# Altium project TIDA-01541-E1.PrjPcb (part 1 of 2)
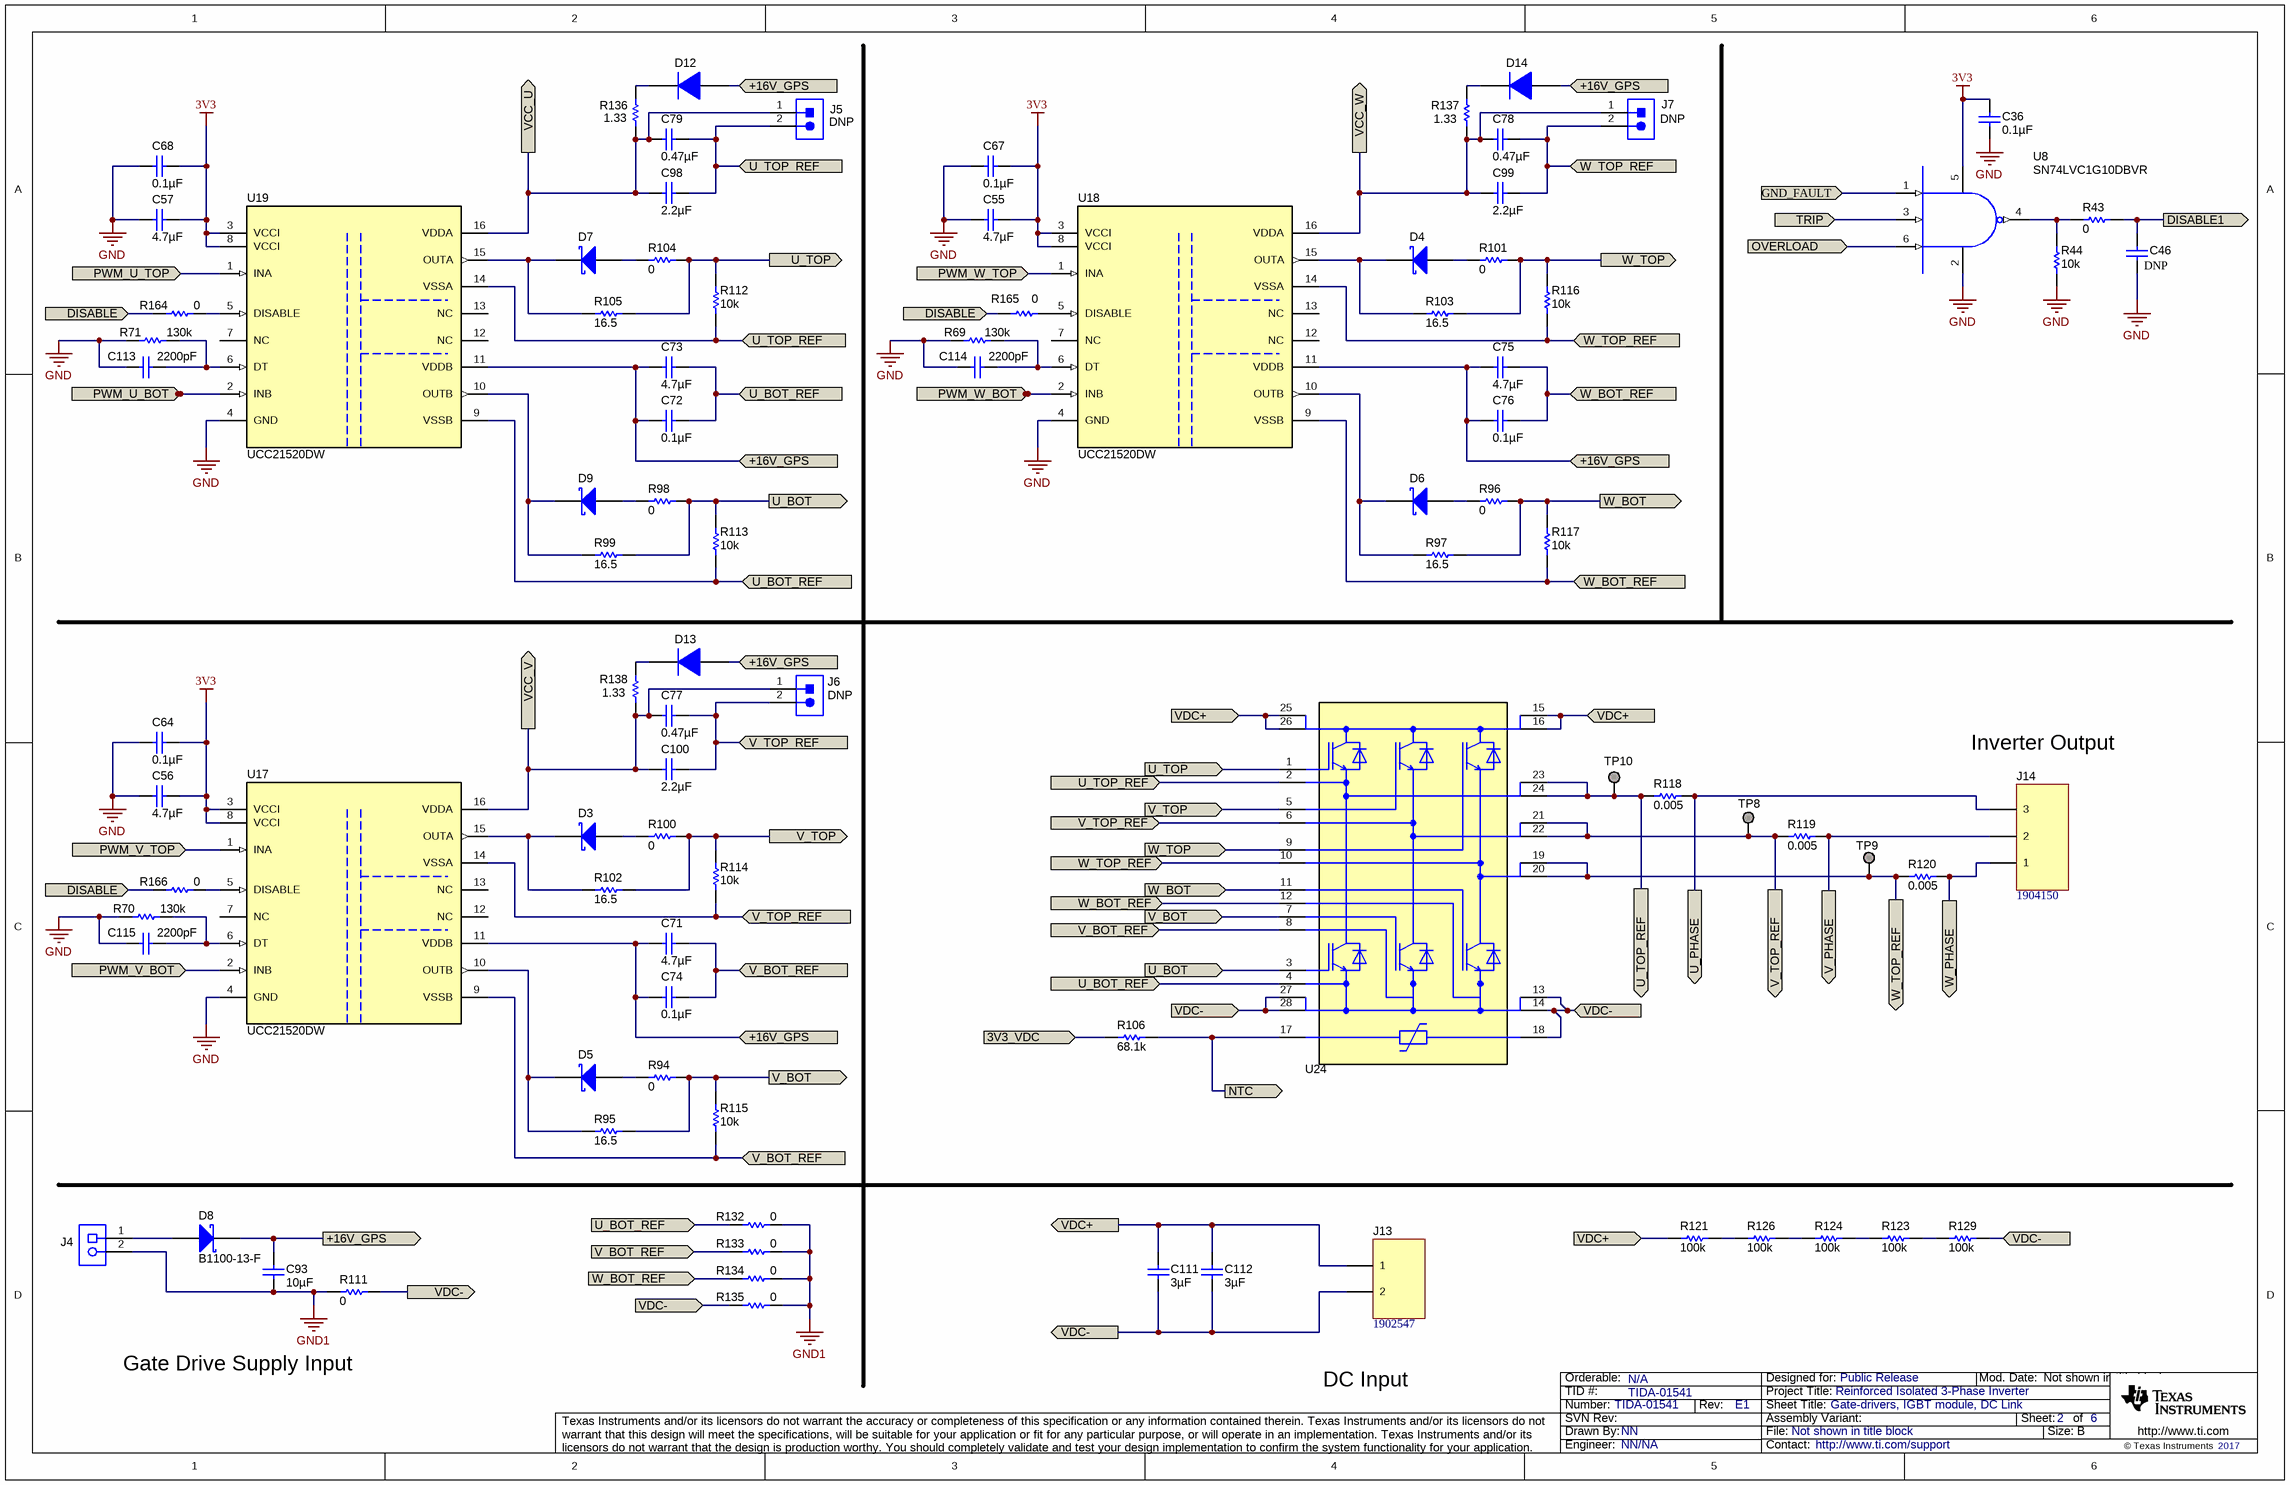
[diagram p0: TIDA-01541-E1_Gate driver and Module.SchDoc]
CopyrightYear: 2017; EVM_Orderable: N/A; PCB_Layout: Avinash N; PCB_Rev: E1; PRJ_Customer: Public Release; PRJ_Engineer: NN/NA; PRJ_Number: TIDA-01541; PRJ_Title: Reinforced Isolated 3-Phase Inverter; SCH_Rev: E1; TechSupport: http://www.ti.com/support; TID: TIDA-01541
5 sheets, 370 parts. Net scope: flat (ports and power ports of the same name join across sheets).
Board file: TIDA-01541-E1.PcbDoc
Sheets:
  TIDA-01541-E1_Gate driver and Module.SchDoc
  TIDA-01541-E1_Current sense.SchDoc
  TIDA-01541-E1_DC BUS and TEMP Sense.SchDoc
  TIDA-01541-E1_MCU Interface.SchDoc
  TIDA-01541-E1_EVM_Hardware.SchDoc

## Sheet TIDA-01541-E1_Gate driver and Module.SchDoc: Gate-drivers, IGBT module, DC Link
size 431 x 279 mm; Date: Not shown in title block; ApprovedBy: Not shown in title block; CheckedBy: Not shown in title block; Author: Not shown in title block; CompanyName: Not shown in title block; DrawnBy: NN; Engineer: Not shown in title block; Organization: Not shown in title block; Address1: Not shown in title block; Address2: Not shown in title block; Address3: Not shown in title block; Address4: Not shown in title block; DocumentNumber: 1; Revision: Use project parameter SCH_Rev; SheetNumber: 2; SheetTotal: 6

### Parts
C36  ValueDisplayed: 0.1µF  [0603]  (hidden comment: GRM188R71H104KA93D)
C46  885012206040  [0603]  (value not drawn)
C55  ValueDisplayed: 4.7µF  [0805_HV]  (hidden comment: C2012X5R1H475K125AB)
C56  ValueDisplayed: 4.7µF  [0805_HV]  (hidden comment: C2012X5R1H475K125AB)
C57  ValueDisplayed: 4.7µF  [0805_HV]  (hidden comment: C2012X5R1H475K125AB)
C64  ValueDisplayed: 0.1µF  [0603]  (hidden comment: GRM188R71H104KA93D)
C67  ValueDisplayed: 0.1µF  [0603]  (hidden comment: GRM188R71H104KA93D)
C68  ValueDisplayed: 0.1µF  [0603]  (hidden comment: GRM188R71H104KA93D)
C71  ValueDisplayed: 4.7µF  [0805_HV]  (hidden comment: C2012X5R1H475K125AB)
C72  ValueDisplayed: 0.1µF  [0603]  (hidden comment: GRM188R71H104KA93D)
C73  ValueDisplayed: 4.7µF  [0805_HV]  (hidden comment: C2012X5R1H475K125AB)
C74  ValueDisplayed: 0.1µF  [0603]  (hidden comment: GRM188R71H104KA93D)
C75  ValueDisplayed: 4.7µF  [0805_HV]  (hidden comment: C2012X5R1H475K125AB)
C76  ValueDisplayed: 0.1µF  [0603]  (hidden comment: GRM188R71H104KA93D)
C77  ValueDisplayed: 0.47µF  [0603]  (hidden comment: C1608X5R1H474K080AB)
C78  ValueDisplayed: 0.47µF  [0603]  (hidden comment: C1608X5R1H474K080AB)
C79  ValueDisplayed: 0.47µF  [0603]  (hidden comment: C1608X5R1H474K080AB)
C93  ValueDisplayed: 10µF  [1210_280]  (hidden comment: C3225X5R1H106K250AB)
C98  ValueDisplayed: 2.2µF  [0805_HV]  (hidden comment: C2012X7R1H225K125AC)
C99  ValueDisplayed: 2.2µF  [0805_HV]  (hidden comment: C2012X7R1H225K125AC)
C100  ValueDisplayed: 2.2µF  [0805_HV]  (hidden comment: C2012X7R1H225K125AC)
C111  ValueDisplayed: 3µF  [B32774_3150x1800x2750]  (hidden comment: B32774D1305K000)
C112  ValueDisplayed: 3µF  [B32774_3150x1800x2750]  (hidden comment: B32774D1305K000)
C113  ValueDisplayed: 2200pF  [0402]  (hidden comment: GRM155R71C222KA01D)
C114  ValueDisplayed: 2200pF  [0402]  (hidden comment: GRM155R71C222KA01D)
C115  ValueDisplayed: 2200pF  [0402]  (hidden comment: GRM155R71C222KA01D)
D3  MSS2P3-M3/89A  [MicroSMP]  (value not drawn)
D4  MSS2P3-M3/89A  [MicroSMP]  (value not drawn)
D5  MSS2P3-M3/89A  [MicroSMP]  (value not drawn)
D6  MSS2P3-M3/89A  [MicroSMP]  (value not drawn)
D7  MSS2P3-M3/89A  [MicroSMP]  (value not drawn)
D8  B1100-13-F  [SMA]
D9  MSS2P3-M3/89A  [MicroSMP]  (value not drawn)
D12  BYG23T-M3/TR  [SMA]  (value not drawn)
D13  BYG23T-M3/TR  [SMA]  (value not drawn)
D14  BYG23T-M3/TR  [SMA]  (value not drawn)
J4  282834-2  [TEC_282834-2]  (value not drawn)
J5  800-10-002-10-001000  [Mill-Max_800-10-002-10-001000]  (value not drawn)
J6  800-10-002-10-001000  [Mill-Max_800-10-002-10-001000]  (value not drawn)
J7  800-10-002-10-001000  [Mill-Max_800-10-002-10-001000]  (value not drawn)
J13  1902547  [PHOENIX_1902547]
J14  1904150  [PHOENIX_1902547]
R43  ValueDisplayed: 0  [0603]  (hidden comment: ERJ-3GEY0R00V)
R44  ValueDisplayed: 10k  [0603]  (hidden comment: RC0603JR-0710KL)
R69  ValueDisplayed: 130k  [0603]  (hidden comment: RC0603FR-07130KL)
R70  ValueDisplayed: 130k  [0603]  (hidden comment: RC0603FR-07130KL)
R71  ValueDisplayed: 130k  [0603]  (hidden comment: RC0603FR-07130KL)
R94  ValueDisplayed: 0  [1206]  (hidden comment: RC1206JR-070RL)
R95  ValueDisplayed: 16.5  [1206]  (hidden comment: ERJ-8ENF16R5V)
R96  ValueDisplayed: 0  [1206]  (hidden comment: RC1206JR-070RL)
R97  ValueDisplayed: 16.5  [1206]  (hidden comment: ERJ-8ENF16R5V)
R98  ValueDisplayed: 0  [1206]  (hidden comment: RC1206JR-070RL)
R99  ValueDisplayed: 16.5  [1206]  (hidden comment: ERJ-8ENF16R5V)
R100  ValueDisplayed: 0  [1206]  (hidden comment: RC1206JR-070RL)
R101  ValueDisplayed: 0  [1206]  (hidden comment: RC1206JR-070RL)
R102  ValueDisplayed: 16.5  [1206]  (hidden comment: ERJ-8ENF16R5V)
R103  ValueDisplayed: 16.5  [1206]  (hidden comment: ERJ-8ENF16R5V)
R104  ValueDisplayed: 0  [1206]  (hidden comment: RC1206JR-070RL)
R105  ValueDisplayed: 16.5  [1206]  (hidden comment: ERJ-8ENF16R5V)
R106  ValueDisplayed: 68.1k  [0603]  (hidden comment: RT0603DRE0768K1L)
R111  ValueDisplayed: 0  [1206]  (hidden comment: RC1206JR-070RL)
R112  ValueDisplayed: 10k  [0603]  (hidden comment: RC0603JR-0710KL)
R113  ValueDisplayed: 10k  [0603]  (hidden comment: RC0603JR-0710KL)
R114  ValueDisplayed: 10k  [0603]  (hidden comment: RC0603JR-0710KL)
R115  ValueDisplayed: 10k  [0603]  (hidden comment: RC0603JR-0710KL)
R116  ValueDisplayed: 10k  [0603]  (hidden comment: RC0603JR-0710KL)
R117  ValueDisplayed: 10k  [0603]  (hidden comment: RC0603JR-0710KL)
R118  ValueDisplayed: 0.005  [PWR44412-2SD]  (hidden comment: PWR4412-2SDR0050F)
R119  ValueDisplayed: 0.005  [PWR44412-2SD]  (hidden comment: PWR4412-2SDR0050F)
R120  ValueDisplayed: 0.005  [PWR44412-2SD]  (hidden comment: PWR4412-2SDR0050F)
R121  ValueDisplayed: 100k  [1206]  (hidden comment: CRCW1206100KJNEA)
R123  ValueDisplayed: 100k  [1206]  (hidden comment: CRCW1206100KJNEA)
R124  ValueDisplayed: 100k  [1206]  (hidden comment: CRCW1206100KJNEA)
R126  ValueDisplayed: 100k  [1206]  (hidden comment: CRCW1206100KJNEA)
R129  ValueDisplayed: 100k  [1206]  (hidden comment: CRCW1206100KJNEA)
R132  ValueDisplayed: 0  [0805_HV]  (hidden comment: ERJ-6GEY0R00V)
R133  ValueDisplayed: 0  [0805_HV]  (hidden comment: ERJ-6GEY0R00V)
R134  ValueDisplayed: 0  [0805_HV]  (hidden comment: ERJ-6GEY0R00V)
R135  ValueDisplayed: 0  [0805_HV]  (hidden comment: ERJ-6GEY0R00V)
R136  ValueDisplayed: 1.33  [0805_HV]  (hidden comment: CRCW08051R33FKEA)
R137  ValueDisplayed: 1.33  [0805_HV]  (hidden comment: CRCW08051R33FKEA)
R138  ValueDisplayed: 1.33  [0805_HV]  (hidden comment: CRCW08051R33FKEA)
R164  ValueDisplayed: 0  [0603]  (hidden comment: ERJ-3GEY0R00V)
R165  ValueDisplayed: 0  [0603]  (hidden comment: ERJ-3GEY0R00V)
R166  ValueDisplayed: 0  [0603]  (hidden comment: ERJ-3GEY0R00V)
TP8  TESTPOINT  [PAD_100mil-40milhole]  (value not drawn)  (no BOM)
TP9  TESTPOINT  [PAD_100mil-40milhole]  (value not drawn)  (no BOM)
TP10  TESTPOINT  [PAD_100mil-40milhole]  (value not drawn)  (no BOM)
U8  SN74LVC1G10DBVR  [DBV0006A_N]
U17  UCC21520DW  [DW0016A_N]
U18  UCC21520DW  [DW0016A_N]
U19  UCC21520DW  [DW0016A_N]
U24  MG1250H-XN2MM  [IXYS_E2]  (value not drawn)

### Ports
3V3_VDC (in), +16V_GPS (in), +16V_GPS (out), DISABLE, DISABLE1 (out), DISABLE (in), GND_FAULT (in), NTC (out), OVERLOAD (in), PWM_U_BOT (in), PWM_U_TOP (in), PWM_V_BOT (in), PWM_V_TOP (in), PWM_W_BOT, PWM_W_TOP, TRIP (in), U_BOT (in), U_BOT (out), U_BOT_REF (in), U_PHASE (out), U_TOP (in), U_TOP (out), U_TOP_REF (in), U_TOP_REF (out), V_BOT (in), V_BOT (out), V_BOT_REF (in), V_PHASE (out), V_TOP (in), V_TOP (out), V_TOP_REF (in), V_TOP_REF (out), VCC_U (out), VCC_V (out), VCC_W (out), VDC+ (in), VDC+ (out), VDC- (in), VDC- (out), W_BOT (in), W_BOT (out), W_BOT_REF (in), W_PHASE (out), W_TOP (in), W_TOP (out), W_TOP_REF (in), W_TOP_REF (out)

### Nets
3V3: C36.1 C55.1 C56.1 C57.1 C64.1 C67.1 C68.1 U8.5(VCC) U17.3(VCCI) U17.8(VCCI) U18.3(VCCI) U18.8(VCCI) U19.3(VCCI) U19.8(VCCI)
GND: C36.2 C46.2 C55.2 C56.2 C57.2 C64.2 C67.2 C68.2 C113.2 C114.2 C115.2 R44.1 R69.1 R70.1 R71.1 U8.2(GND) U17.4(GND) U18.4(GND) U19.4(GND)
GND1: C93.2 J4.2 R111.1 R132.2 R133.2 R134.2 R135.2
3V3_VDC: R106.1 ; port 3V3_VDC
+16V_GPS: C71.2 C72.2 C73.2 C74.2 C75.2 C76.2 C93.1 D8.1(K) D12.2(A) D13.2(A) D14.2(A) U17.11(VDDB) U18.11(VDDB) U19.11(VDDB) ; port +16V_GPS
DISABLE: R164.1 R165.1 R166.1 ; port DISABLE
DISABLE1: C46.1 R43.2 ; port DISABLE1
GND_FAULT: U8.1(A) ; port GND_FAULT
NTC: R106.2 U24.17 ; port NTC
OVERLOAD: U8.6(C) ; port OVERLOAD
PWM_U_BOT: U19.2(INB) ; port PWM_U_BOT
PWM_U_TOP: U19.1(INA) ; port PWM_U_TOP
PWM_V_BOT: U17.2(INB) ; port PWM_V_BOT
PWM_V_TOP: U17.1(INA) ; port PWM_V_TOP
PWM_W_BOT: U18.2(INB) ; port PWM_W_BOT
PWM_W_TOP: U18.1(INA) ; port PWM_W_TOP
TRIP: U8.3(B) ; port TRIP
U_BOT: R98.2 R99.2 R113.2 U24.3 ; port U_BOT
U_BOT_REF: C72.1 C73.1 R113.1 R132.1 U19.9(VSSB) U24.4 ; port U_BOT_REF
U_PHASE: J14.3 R118.1 ; port U_PHASE
U_TOP: R104.2 R105.2 R112.2 U24.1 ; port U_TOP
U_TOP_REF: C79.1 C98.1 J5.2 R112.1 R118.2 TP10.1 U19.14(VSSA) U24.2 U24.23 U24.24 ; port U_TOP_REF
V_BOT: R94.2 R95.2 R115.2 U24.7 ; port V_BOT
V_BOT_REF: C71.1 C74.1 R115.1 R133.1 U17.9(VSSB) U24.8 ; port V_BOT_REF
V_PHASE: J14.2 R119.2 ; port V_PHASE
V_TOP: R100.2 R102.2 R114.2 U24.5 ; port V_TOP
V_TOP_REF: C77.1 C100.1 J6.2 R114.1 R119.1 TP8.1 U17.14(VSSA) U24.6 U24.21 U24.22 ; port V_TOP_REF
VCC_U: C79.2 C98.2 J5.1 R136.1 U19.16(VDDA) ; port VCC_U
VCC_V: C77.2 C100.2 J6.1 R138.1 U17.16(VDDA) ; port VCC_V
VCC_W: C78.2 C99.2 J7.1 R137.1 U18.16(VDDA) ; port VCC_W
VDC+: C111.1 C112.1 J13.1 R121.1 U24.15 U24.16 U24.25 U24.26 ; port VDC+
VDC-: C111.2 C112.2 J13.2 R111.2 R129.2 R135.1 U24.13 U24.14 U24.18 U24.27 U24.28 ; port VDC-
W_BOT: R96.2 R97.2 R117.2 U24.11 ; port W_BOT
W_BOT_REF: C75.1 C76.1 R117.1 R134.1 U18.9(VSSB) U24.12 ; port W_BOT_REF
W_PHASE: J14.1 R120.2 ; port W_PHASE
W_TOP: R101.2 R103.2 R116.2 U24.9 ; port W_TOP
W_TOP_REF: C78.1 C99.1 J7.2 R116.1 R120.1 TP9.1 U18.14(VSSA) U24.10 U24.19 U24.20 ; port W_TOP_REF
NetC113_1: C113.1 R71.2 U19.6(DT)
NetC114_1: C114.1 R69.2 U18.6(DT)
NetC115_1: C115.1 R70.2 U17.6(DT)
NetD3_1: D3.1(K) R102.1 U17.15(OUTA)
NetD3_2: D3.2(A) R100.1
NetD4_1: D4.1(K) R103.1 U18.15(OUTA)
NetD4_2: D4.2(A) R101.1
NetD5_1: D5.1(K) R95.1 U17.10(OUTB)
NetD5_2: D5.2(A) R94.1
NetD6_1: D6.1(K) R97.1 U18.10(OUTB)
NetD6_2: D6.2(A) R96.1
NetD7_1: D7.1(K) R105.1 U19.15(OUTA)
NetD7_2: D7.2(A) R104.1
NetD8_2: D8.2(A) J4.1
NetD9_1: D9.1(K) R99.1 U19.10(OUTB)
NetD9_2: D9.2(A) R98.1
NetD12_1: D12.1(K) R136.2
NetD13_1: D13.1(K) R138.2
NetD14_1: D14.1(K) R137.2
NetR43_1: R43.1 R44.2 U8.4(Y)
NetR121_2: R121.2 R126.1
NetR123_1: R123.1 R124.2
NetR123_2: R123.2 R129.1
NetR124_1: R124.1 R126.2
NetR164_2: R164.2 U19.5(DISABLE)
NetR165_2: R165.2 U18.5(DISABLE)
NetR166_2: R166.2 U17.5(DISABLE)

Not connected (* = marked no-connect by the designer): U17 7(NC) 12(NC) 13(NC); U18 7(NC) 12(NC) 13(NC); U19 7(NC) 12(NC) 13(NC)

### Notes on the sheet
- Inverter Output
- Gate Drive Supply Input
- DC Input

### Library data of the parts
C36 C64 C67 C68 C72 C74 C76 = GRM188R71H104KA93D: CAP, CERM, 0.1 µF, 50 V, +/- 10%, X7R, 0603; Manufacturer: MuRata; Polarized: N; CompType: Capacitor; Value: 0.1uF; U/M: EA; Cap_F: 0.0000001; Tolerance_%: 10; Value1: Unknown; VDC_V: 50; Value2: 50V; TaMin_C: -55; TaMax_C: 125; AEC Category: Q200; SizeArea_mm2: 1.28; SizeAreaWB_mm2: 4.68; SizeX_mm: 1.6; SizeY_mm: 0.8; SizeZ_mm: 1
C46 = 885012206040: CAP, CERM, 0.01 µF, 16 V, +/- 10%, X7R, 0603; Manufacturer: Wurth Elektronik; Polarized: N; CompType: Capacitor; Value: 0.01uF; ValueDisplayed: 0.01µF; U/M: EA; Cap_F: 0.00000001; Tolerance_%: 10; Value1: Unknown; VDC_V: 16; Value2: 16V; TaMin_C: -55; TaMax_C: 125; AEC Category: Q200
C55-C57 C71 C73 C75 = C2012X5R1H475K125AB: CAP, CERM, 4.7 µF, 50 V, +/- 10%, X5R, 0805; Manufacturer: TDK; Polarized: N; CompType: Capacitor; Value: 4.7uF; U/M: EA; Cap_F: 0.0000047; Tolerance_%: 10; Value1: Unknown; VDC_V: 50; Value2: 50V; TaMin_C: -55; TaMax_C: 85; Cap_Case: 0805; AEC Category: Q200
C77-C79 = C1608X5R1H474K080AB: CAP, CERM, 0.47 µF, 50 V, +/- 10%, X5R, 0603; Manufacturer: TDK; Polarized: N; CompType: Capacitor; Value: 0.47uF; U/M: EA; Cap_F: 0.00000047; Tolerance_%: 10; ESR_ohm: 0.010974; Value1: 0.010974 ohm; VDC_V: 50; Value2: 50V; IRMS_A: 1.57483; TaMin_C: -55; TaMax_C: 85; AEC Category: Q200; SizeArea_mm2: 1.28; SizeAreaWB_mm2: 4.68; SizeX_mm: 1.6; SizeY_mm: 0.8; SizeZ_mm: 1
C93 = C3225X5R1H106K250AB: CAP, CERM, 10 µF, 50 V, +/- 10%, X5R, 1210; Manufacturer: TDK; Polarized: N; CompType: Capacitor; Value: 10uF; U/M: EA; Cap_F: 0.00001; Tolerance_%: 10; Value1: Unknown; VDC_V: 50; Value2: 50V; TaMin_C: -55; TaMax_C: 85; Cap_Case: 1210; AEC Category: Q200
C98-C100 = C2012X7R1H225K125AC: CAP, CERM, 2.2 µF, 50 V, +/- 10%, X7R, 0805; Manufacturer: TDK; Polarized: N; CompType: Capacitor; Value: 2.2uF; U/M: EA; Cap_F: 0.0000022; Tolerance_%: 10; ESR_ohm: 0.00366; Value1: 0.00366 ohm; VDC_V: 50; Value2: 50V; IRMS_A: 3.41207; TaMin_C: -55; TaMax_C: 125; Cap_Case: 0805; AEC Category: Q200; SizeArea_mm2: 2.5; SizeAreaWB_mm2: 6.75; SizeX_mm: 2; SizeY_mm: 1.25; SizeZ_mm: 1.45
C111 C112 = B32774D1305K000: CAP, Film, 3 µF, 1300 V, +/- 10%, 0.016 ohm, TH; Manufacturer: TDK; Polarized: N; CompType: Capacitor; Value: 3uF; U/M: EA; Cap_F: 0.000003; Tolerance_%: 10; VDC_V: 1300; Value2: 1300V; ESR_ohm: 0.016; IRMS_A: 7; TaMin_C: -40; TaMax_C: 105; Cap_Case: 31.5x18x27.5mm; AEC Category: Q200
C113-C115 = GRM155R71C222KA01D: CAP, CERM, 2200 pF, 16 V, +/- 10%, X7R, 0402; Manufacturer: MuRata; Polarized: N; CompType: Capacitor; Value: 2200pF; U/M: EA; Cap_F: 0.0000000022; Tolerance_%: 10; Value1: Unknown; VDC_V: 16; Value2: 16V; TaMin_C: -55; TaMax_C: 125; AEC Category: Q200; SizeArea_mm2: 0.5; SizeAreaWB_mm2: 3; SizeX_mm: 1; SizeZ_mm: 0.6
D3-D7 D9 = MSS1P3L-M3/89A: Diode, Schottky, 30 V, 2 A, AEC-Q101, MicroSMP; Manufacturer: Vishay-Semiconductor; Alternate PartNumber: MSS1P6-M3/89AGICT-ND; U/M: EA; Vf_V: 0.6; Value: 30V; Value1: 2A; Value2: 0.6V; Io_A: 1; Vr_V: 30; TJmax_C: 150; RJC_CperW: 40; AEC Category: Q101; AEC Qualified: Y
D8 = B1100-13-F: Diode, Schottky, 100 V, 1 A, SMA; Manufacturer: Diodes Inc.; U/M: EA; Vf_V: 0.79; Value: 100V; Value1: 1A; Value2: 0.79V; Io_A: 1; Vr_V: 100; TJmax_C: 150; RJC_CperW: 25; AEC Category: Q101
D12-D14 = BYG23T-M3/TR: Diode, Ultrafast, 1300 V, 1 A, SMA; Manufacturer: Vishay-Semiconductor; Alternate Manufacturer: Central Semiconductor Corp; Alternate PartNumber: CMR1U-13M TR13-CT-ND; U/M: EA; Vf_V: 1.9; Value: 1300V; Value1: 1A; Value2: 1.9V; Io_A: 1; Vr_V: 1300; TJmax_C: 150; AEC Category: Q101; AEC Qualified: N
J4 = 282834-2: Terminal Block, 2x1, 2.54mm, TH; Manufacturer: TE Connectivity; SymbolCreator: a0412235
J5-J7 = 800-10-002-10-001000: Header, 100mil, 2x1, TH; Manufacturer: Mill-Max; SymbolCreator: a0412235
J13 = 691133810002: Horizontal Cable Entry with Pressure Clamp, Serie 1338 - 10.00 mm; Manufacturer: Phoenix Contact; ComponentLink1 Description: Manufacturer; ComponentLink2 Description: Datasheet; NoPins: 2
J14 = 691131810003: Horizontal Cable Entry with Pressure Clamp, Serie 1318 - 10.00 mm; Manufacturer: Phoenix Contact; ComponentLink1 Description: Manufacturer; NoPins: 3
R43 = ERJ-3GEY0R00V: RES, 0, 5%, 0.1 W, 0603; Manufacturer: Panasonic; CompType: Resistor; Value: 0; Value_Code: 0000; Tolerance_%: 5; Power_W: 0.1; Value2: 0.1W; VDC_V: 50; TempCo: 600 ppm/C; EIA_Code: E24; U/M: EA; AEC Category: Q200; SizeArea_mm2: 1.28; SizeX_mm: 1.6; SizeY_mm: 0.8; SizeZ_mm: 1
R44 R112-R117 = RC0603JR-0710KL: RES, 10 k, 5%, 0.1 W, 0603; Manufacturer: Yageo America; CompType: Resistor; Value: 10k; Res_ohm: 10000; Value_Code: 10k0; Tolerance_%: 5; Power_W: 0.1; Value2: 0.1W; VDC_V: 50; TempCo: 100 ppm/C; EIA_Code: E24; U/M: EA; AEC Category: Q200; SizeArea_mm2: 1.28; SizeX_mm: 1.6; SizeY_mm: 0.8; SizeZ_mm: 1
R69-R71 = RC0603FR-07130KL: RES, 130 k, 1%, 0.1 W, 0603; Manufacturer: Yageo America; CompType: Resistor; Value: 130k; Res_ohm: 130000; Tolerance_%: 1; Power_W: 0.1; Value2: 0.1W; VDC_V: 150; TempCo: 200 ppm/C; EIA_Code: E96; U/M: EA; AEC Category: Q200; SizeArea_mm2: 1.28; SizeX_mm: 1.6; SizeY_mm: 0.8
R94 R96 R98 R100 R101 R104 R111 = RC1206JR-070RL: RES, 0, 5%, 0.25 W, 1206; Manufacturer: Yageo America; CompType: Resistor; Value: 0; Value_Code: 0000; Tolerance_%: 5; Power_W: 0.25; Value2: 0.25W; VDC_V: 200; TempCo: 200 ppm/C; EIA_Code: E24; U/M: EA; AEC Category: Q200; SizeArea_mm2: 5.12; SizeX_mm: 3.2; SizeY_mm: 1.6; SizeZ_mm: 1.35
R95 R97 R99 R102 R103 R105 = ERJ-8ENF16R5V: RES, 16.5, 1%, 0.25 W, 1206; Manufacturer: Panasonic; CompType: Resistor; Value: 16.5; Value_Code: 16R5; Tolerance_%: 1; Power_W: 0.25; Value2: 0.25W; VDC_V: 200; TempCo: 100 ppm/C; EIA_Code: E96; U/M: EA; AEC Category: Q200; SizeArea_mm2: 5.12; SizeX_mm: 3.2; SizeY_mm: 1.6; SizeZ_mm: 1.35
R106 = RT0603DRE0768K1L: RES, 68.1 k, 0.5%, 0.1 W, 0603; Manufacturer: Yageo America; CompType: Resistor; Value: 68.1k; Res_ohm: 68100; Value_Code: 68k1; Tolerance_%: 0.5; Power_W: 0.1; Value2: 0.1W; VDC_V: 75; TempCo: 50 ppm/C; EIA_Code: E192; U/M: EA; AEC Category: Q200; SizeArea_mm2: 1.28; SizeX_mm: 1.6; SizeY_mm: 0.8; SizeZ_mm: 1
R118-R120 = PWR4412-2SDR0050F: RES, 0.005, 1%, 5 W, 20.32x4.80mm; Manufacturer: Bourns; CompType: Resistor; Value: 0.005; Value_Code: 5L000; Tolerance_%: 1; Power_W: 5; Value2: 5W; TempCo: 20 ppm/C; EIA_Code: E96; U/M: EA; AEC Category: Q200; AEC Qualified: N
R121 R123 R124 R126 R129 = CRCW1206100KJNEA: RES, 100 k, 5%, 0.25 W, 1206; Manufacturer: Vishay-Dale; CompType: Resistor; Value: 100k; Res_ohm: 100000; Tolerance_%: 5; Power_W: 0.25; Value2: 0.25W; VDC_V: 200; TempCo: 200 ppm/C; EIA_Code: E24; U/M: EA; AEC Category: Q200
R132-R135 = ERJ-6GEY0R00V: RES, 0, 5%, 0.125 W, 0805; Manufacturer: Panasonic; CompType: Resistor; Value: 0; Value_Code: 0000; Tolerance_%: 5; Power_W: 0.125; Value2: 0.125W; VDC_V: 150; TempCo: 600 ppm/C; EIA_Code: E24; U/M: EA; AEC Category: Q200; SizeArea_mm2: 2.5; SizeX_mm: 2; SizeY_mm: 1.25; SizeZ_mm: 1.45
R136-R138 = CRCW08051R33FKEA: RES, 1.33, 1%, 0.125 W, 0805; Manufacturer: Vishay-Dale; CompType: Resistor; Value: 1.33; Value_Code: 1R33; Tolerance_%: 1; Power_W: 0.125; Value2: 0.125W; VDC_V: 150; TempCo: 100 ppm/C; EIA_Code: E96; U/M: EA; AEC Category: Q200
R164-R166 = ERJ-3GEY0R00V: RES, 0, 5%, 0.1 W, 0603; Manufacturer: Panasonic; CompType: Resistor; Value: 0; Value_Code: 0000; Tolerance_%: 5; Power_W: 0.1; Value2: 0.1W; VDC_V: 50; TempCo: 600 ppm/C; SizeArea_mm2: 1.28; SizeX_mm: 1.6; SizeY_mm: 0.8; SizeZ_mm: 1; EIA_Code: E24; U/M: EA; AEC Category: Q200
TP8-TP10 = PAD_100mil-40milhole: 100mil pad, 40mil hole; Manufacturer: Any
U8 = SN74LVC1G10DBVR: Single 3-Input Positive-NAND Gate, DBV0006A; Manufacturer: Texas Instruments; SymbolVersion: Altium; SizeArea_mm2: 8.12; SizeAreaWB_mm2: 14.82; SizeX_mm: 2.8; SizeY_mm: 2.9; SizeZ_mm: 1.45; CompType: IC; U/M: EA
U17-U19 = UCC21520DW: 4A/6A, 5KVrms Dual Isolated-channel Universal Gate Driver, DW0016A; Manufacturer: Texas Instruments; SymbolCreator: a0799628; CompType: IC; U/M: EA
U24 = MWI 50-12T7T: IGBT MOD 1200V 50A PKG H CRCT:X; Manufacturer: Littelfuse Inc.; SymbolCreator: Altium

## Sheet TIDA-01541-E1_Current sense.SchDoc: Current Sense
size 431 x 279 mm; Date: Not shown in title block; ApprovedBy: Not shown in title block; CheckedBy: Not shown in title block; Author: Not shown in title block; CompanyName: Not shown in title block; DrawnBy: NN; Engineer: Not shown in title block; Organization: Not shown in title block; Address1: Not shown in title block; Address2: Not shown in title block; Address3: Not shown in title block; Address4: Not shown in title block; DocumentNumber: 1; Revision: Use project parameter SCH_Rev; SheetNumber: 3; SheetTotal: 6; PageSetup: Record=PageOptions¦CenterHorizontal=True¦CenterVertical=True¦PrintScale=1.00¦XCorrection=1.00¦YCorrection=1.00¦PrintKind=0¦BorderSize=5000000¦LeftOffset=0¦BottomOffset=0¦Orientation=2¦PaperLength=1000¦PaperWidth=1000¦Scale=100¦PaperSource=15¦PrintQuality=600¦MediaType=1¦DitherType=10¦PaperKind=Letter¦PrintScaleMode=1
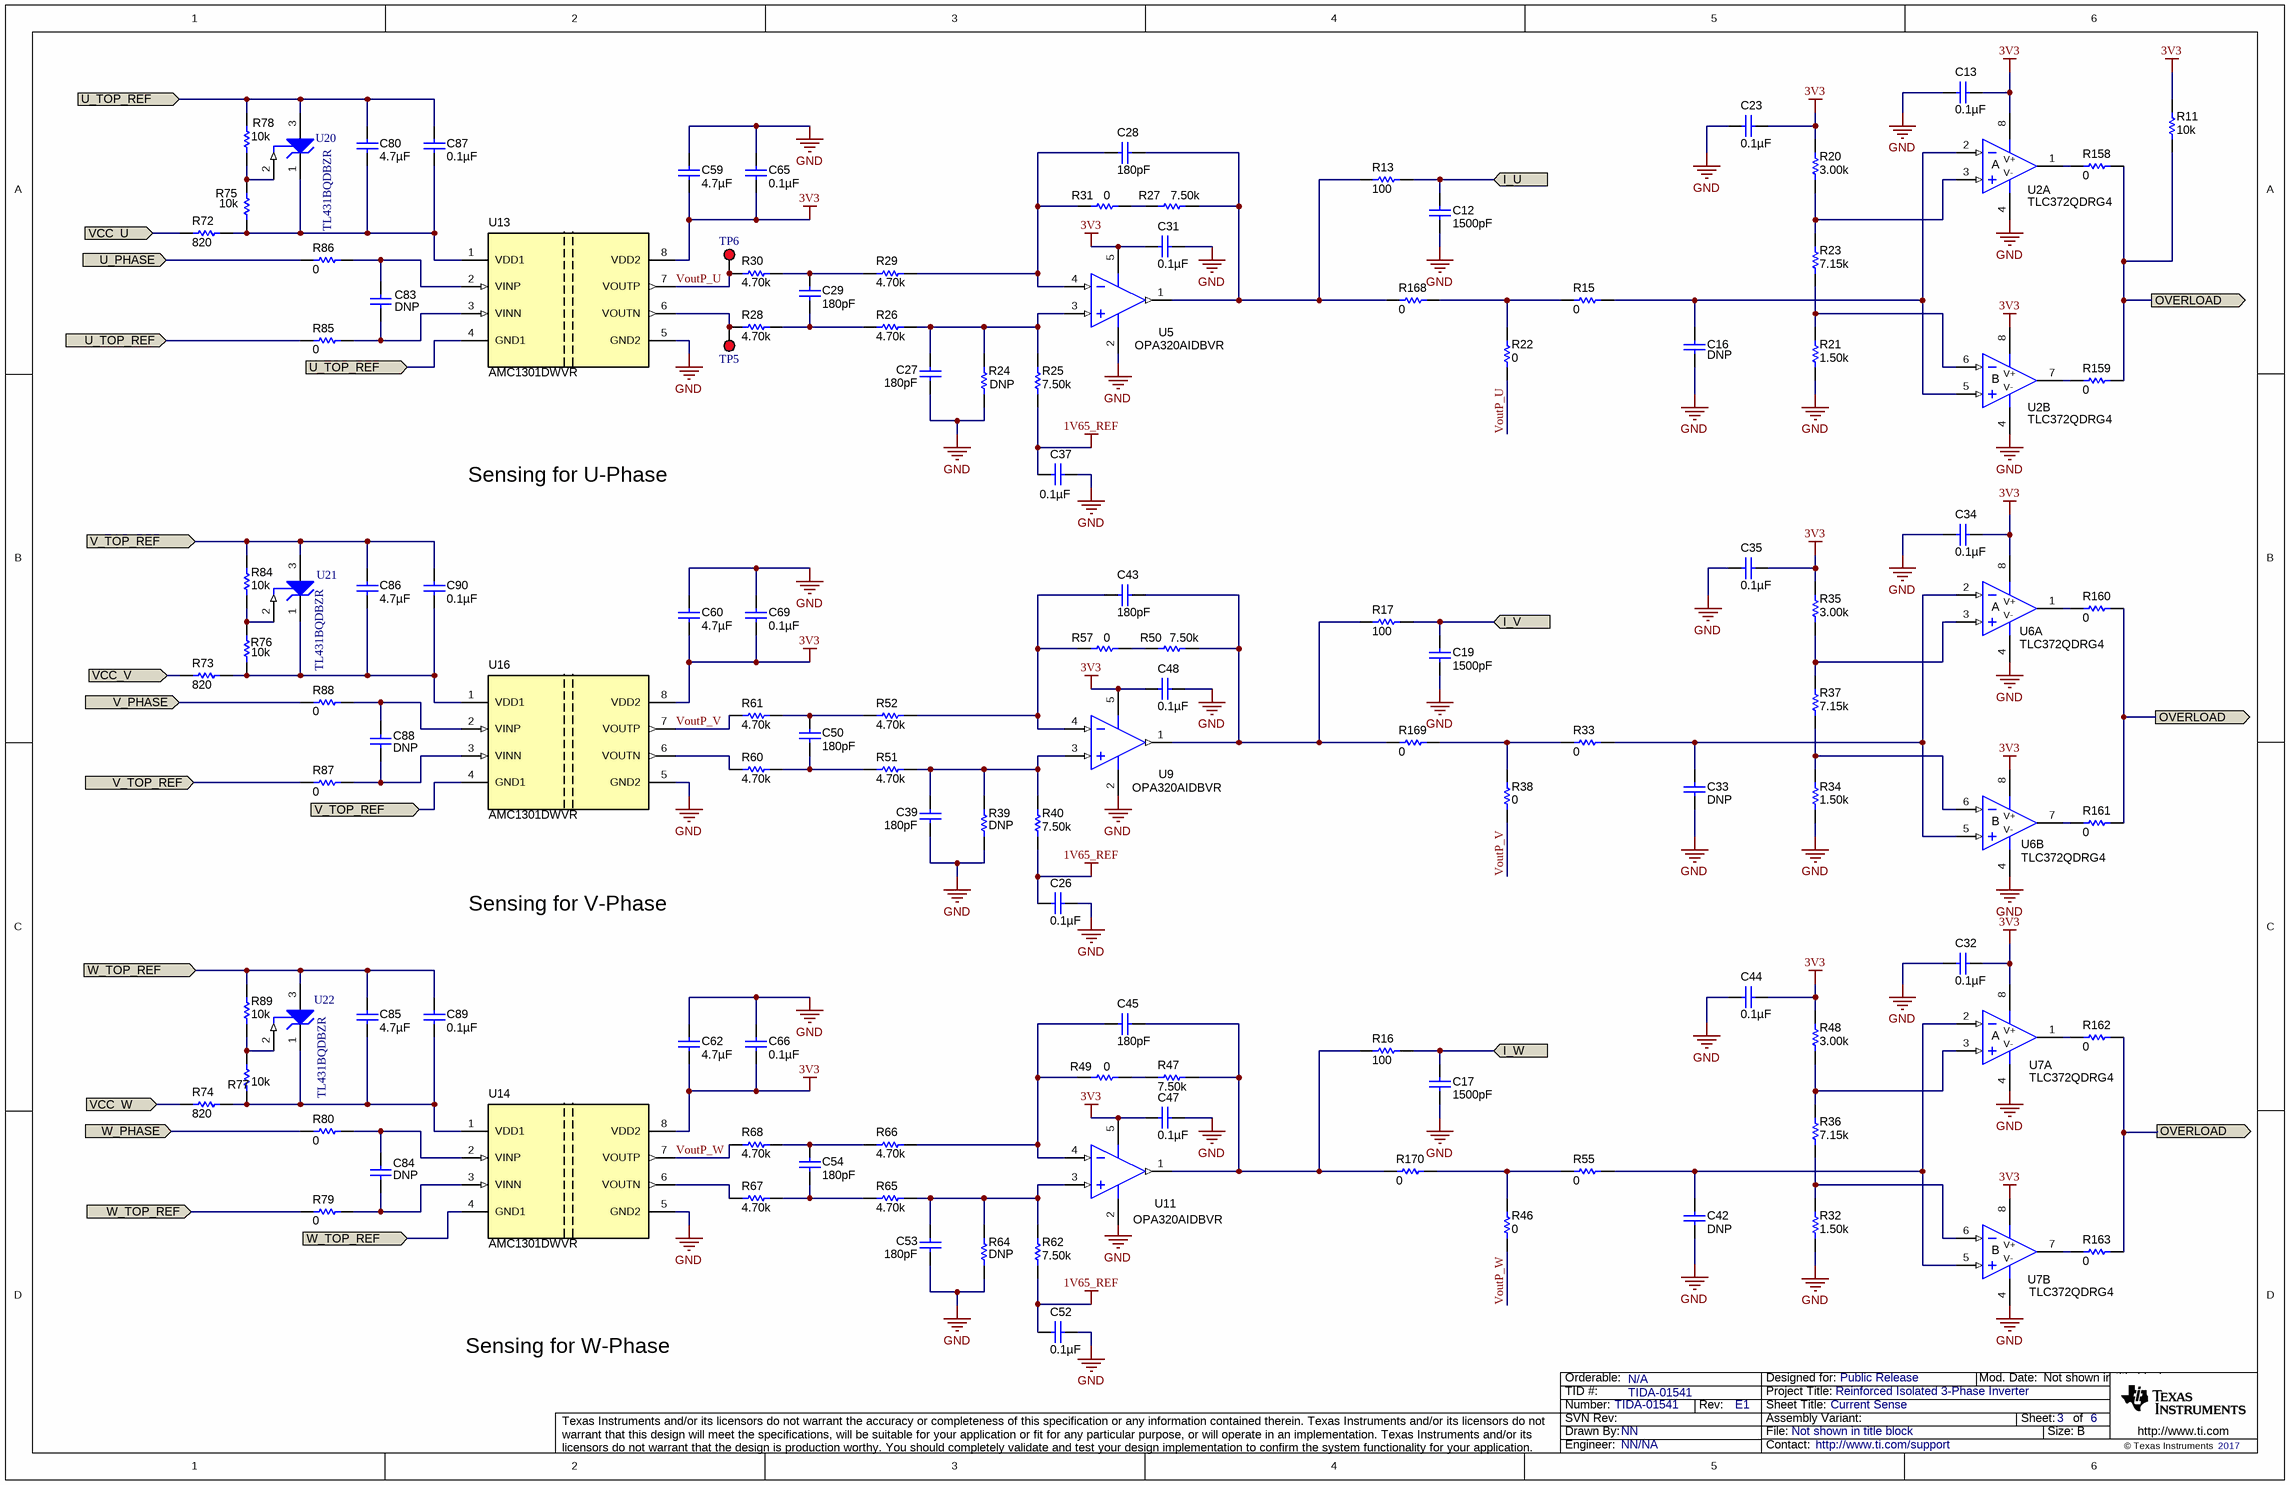
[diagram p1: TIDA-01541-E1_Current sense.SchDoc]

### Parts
C12  ValueDisplayed: 1500pF  [0603]  (hidden comment: 06031C152JAT2A)
C13  ValueDisplayed: 0.1µF  [0603]  (hidden comment: GRM188R71H104KA93D)
C16  885012206040  [0603]  (value not drawn)
C17  ValueDisplayed: 1500pF  [0603]  (hidden comment: 06031C152JAT2A)
C19  ValueDisplayed: 1500pF  [0603]  (hidden comment: 06031C152JAT2A)
C23  ValueDisplayed: 0.1µF  [0603]  (hidden comment: GRM188R71H104KA93D)
C26  ValueDisplayed: 0.1µF  [0603]  (hidden comment: GRM188R71H104KA93D)
C27  ValueDisplayed: 180pF  [0603]  (hidden comment: 06035A181JAT2A)
C28  ValueDisplayed: 180pF  [0603]  (hidden comment: 06035A181JAT2A)
C29  ValueDisplayed: 180pF  [0603]  (hidden comment: 06035A181JAT2A)
C31  ValueDisplayed: 0.1µF  [0603]  (hidden comment: GRM188R71H104KA93D)
C32  ValueDisplayed: 0.1µF  [0603]  (hidden comment: GRM188R71H104KA93D)
C33  885012206040  [0603]  (value not drawn)
C34  ValueDisplayed: 0.1µF  [0603]  (hidden comment: GRM188R71H104KA93D)
C35  ValueDisplayed: 0.1µF  [0603]  (hidden comment: GRM188R71H104KA93D)
C37  ValueDisplayed: 0.1µF  [0603]  (hidden comment: GRM188R71H104KA93D)
C39  ValueDisplayed: 180pF  [0603]  (hidden comment: 06035A181JAT2A)
C42  885012206040  [0603]  (value not drawn)
C43  ValueDisplayed: 180pF  [0603]  (hidden comment: 06035A181JAT2A)
C44  ValueDisplayed: 0.1µF  [0603]  (hidden comment: GRM188R71H104KA93D)
C45  ValueDisplayed: 180pF  [0603]  (hidden comment: 06035A181JAT2A)
C47  ValueDisplayed: 0.1µF  [0603]  (hidden comment: GRM188R71H104KA93D)
C48  ValueDisplayed: 0.1µF  [0603]  (hidden comment: GRM188R71H104KA93D)
C50  ValueDisplayed: 180pF  [0603]  (hidden comment: 06035A181JAT2A)
C52  ValueDisplayed: 0.1µF  [0603]  (hidden comment: GRM188R71H104KA93D)
C53  ValueDisplayed: 180pF  [0603]  (hidden comment: 06035A181JAT2A)
C54  ValueDisplayed: 180pF  [0603]  (hidden comment: 06035A181JAT2A)
C59  ValueDisplayed: 4.7µF  [0805_HV]  (hidden comment: C2012X5R1H475K125AB)
C60  ValueDisplayed: 4.7µF  [0805_HV]  (hidden comment: C2012X5R1H475K125AB)
C62  ValueDisplayed: 4.7µF  [0805_HV]  (hidden comment: C2012X5R1H475K125AB)
C65  ValueDisplayed: 0.1µF  [0603]  (hidden comment: GRM188R71H104KA93D)
C66  ValueDisplayed: 0.1µF  [0603]  (hidden comment: GRM188R71H104KA93D)
C69  ValueDisplayed: 0.1µF  [0603]  (hidden comment: GRM188R71H104KA93D)
C80  ValueDisplayed: 4.7µF  [0805_HV]  (hidden comment: C2012X5R1H475K125AB)
C83  885012206040  [0603]  (value not drawn)
C84  885012206040  [0603]  (value not drawn)
C85  ValueDisplayed: 4.7µF  [0805_HV]  (hidden comment: C2012X5R1H475K125AB)
C86  ValueDisplayed: 4.7µF  [0805_HV]  (hidden comment: C2012X5R1H475K125AB)
C87  ValueDisplayed: 0.1µF  [0603]  (hidden comment: GRM188R71H104KA93D)
C88  885012206040  [0603]  (value not drawn)
C89  ValueDisplayed: 0.1µF  [0603]  (hidden comment: GRM188R71H104KA93D)
C90  ValueDisplayed: 0.1µF  [0603]  (hidden comment: GRM188R71H104KA93D)
R11  ValueDisplayed: 10k  [0603]  (hidden comment: RC0603JR-0710KL)
R13  ValueDisplayed: 100  [0603]  (hidden comment: RC0603FR-07100RL)
R15  ValueDisplayed: 0  [0603]  (hidden comment: ERJ-3GEY0R00V)
R16  ValueDisplayed: 100  [0603]  (hidden comment: RC0603FR-07100RL)
R17  ValueDisplayed: 100  [0603]  (hidden comment: RC0603FR-07100RL)
R20  ValueDisplayed: 3.00k  [0603]  (hidden comment: RC0603FR-073KL)
R21  ValueDisplayed: 1.50k  [0603]  (hidden comment: ERJ-3EKF1501V)
R22  ValueDisplayed: 0  [0603]  (hidden comment: ERJ-3GEY0R00V)
R23  ValueDisplayed: 7.15k  [0603]  (hidden comment: RT0603BRD077K15L)
R24  ERJ-3EKF7501V  [0603]  (value not drawn)
R25  ValueDisplayed: 7.50k  [0603]  (hidden comment: ERJ-3EKF7501V)
R26  ValueDisplayed: 4.70k  [0603]  (hidden comment: RC0603FR-074K7L)
R27  ValueDisplayed: 7.50k  [0603]  (hidden comment: ERJ-3EKF7501V)
R28  ValueDisplayed: 4.70k  [0603]  (hidden comment: RC0603FR-074K7L)
R29  ValueDisplayed: 4.70k  [0603]  (hidden comment: RC0603FR-074K7L)
R30  ValueDisplayed: 4.70k  [0603]  (hidden comment: RC0603FR-074K7L)
R31  ValueDisplayed: 0  [0603]  (hidden comment: ERJ-3GEY0R00V)
R32  ValueDisplayed: 1.50k  [0603]  (hidden comment: ERJ-3EKF1501V)
R33  ValueDisplayed: 0  [0603]  (hidden comment: ERJ-3GEY0R00V)
R34  ValueDisplayed: 1.50k  [0603]  (hidden comment: ERJ-3EKF1501V)
R35  ValueDisplayed: 3.00k  [0603]  (hidden comment: RC0603FR-073KL)
R36  ValueDisplayed: 7.15k  [0603]  (hidden comment: RT0603BRD077K15L)
R37  ValueDisplayed: 7.15k  [0603]  (hidden comment: RT0603BRD077K15L)
R38  ValueDisplayed: 0  [0603]  (hidden comment: ERJ-3GEY0R00V)
R39  ERJ-3EKF7501V  [0603]  (value not drawn)
R40  ValueDisplayed: 7.50k  [0603]  (hidden comment: ERJ-3EKF7501V)
R46  ValueDisplayed: 0  [0603]  (hidden comment: ERJ-3GEY0R00V)
R47  ValueDisplayed: 7.50k  [0603]  (hidden comment: ERJ-3EKF7501V)
R48  ValueDisplayed: 3.00k  [0603]  (hidden comment: RC0603FR-073KL)
R49  ValueDisplayed: 0  [0603]  (hidden comment: ERJ-3GEY0R00V)
R50  ValueDisplayed: 7.50k  [0603]  (hidden comment: ERJ-3EKF7501V)
R51  ValueDisplayed: 4.70k  [0603]  (hidden comment: RC0603FR-074K7L)
R52  ValueDisplayed: 4.70k  [0603]  (hidden comment: RC0603FR-074K7L)
R55  ValueDisplayed: 0  [0603]  (hidden comment: ERJ-3GEY0R00V)
R57  ValueDisplayed: 0  [0603]  (hidden comment: ERJ-3GEY0R00V)
R60  ValueDisplayed: 4.70k  [0603]  (hidden comment: RC0603FR-074K7L)
R61  ValueDisplayed: 4.70k  [0603]  (hidden comment: RC0603FR-074K7L)
R62  ValueDisplayed: 7.50k  [0603]  (hidden comment: ERJ-3EKF7501V)
R64  ERJ-3EKF7501V  [0603]  (value not drawn)
R65  ValueDisplayed: 4.70k  [0603]  (hidden comment: RC0603FR-074K7L)
R66  ValueDisplayed: 4.70k  [0603]  (hidden comment: RC0603FR-074K7L)
R67  ValueDisplayed: 4.70k  [0603]  (hidden comment: RC0603FR-074K7L)
R68  ValueDisplayed: 4.70k  [0603]  (hidden comment: RC0603FR-074K7L)
R72  ValueDisplayed: 820  [0805_HV]  (hidden comment: CRCW0805820RJNEA)
R73  ValueDisplayed: 820  [0805_HV]  (hidden comment: CRCW0805820RJNEA)
R74  ValueDisplayed: 820  [0805_HV]  (hidden comment: CRCW0805820RJNEA)
R75  ValueDisplayed: 10k  [0603]  (hidden comment: RC0603JR-0710KL)
R76  ValueDisplayed: 10k  [0603]  (hidden comment: RC0603JR-0710KL)
R77  ValueDisplayed: 10k  [0603]  (hidden comment: RC0603JR-0710KL)
R78  ValueDisplayed: 10k  [0603]  (hidden comment: RC0603JR-0710KL)
R79  ValueDisplayed: 0  [0603]  (hidden comment: ERJ-3GEY0R00V)
R80  ValueDisplayed: 0  [0603]  (hidden comment: ERJ-3GEY0R00V)
R84  ValueDisplayed: 10k  [0603]  (hidden comment: RC0603JR-0710KL)
R85  ValueDisplayed: 0  [0603]  (hidden comment: ERJ-3GEY0R00V)
R86  ValueDisplayed: 0  [0603]  (hidden comment: ERJ-3GEY0R00V)
R87  ValueDisplayed: 0  [0603]  (hidden comment: ERJ-3GEY0R00V)
R88  ValueDisplayed: 0  [0603]  (hidden comment: ERJ-3GEY0R00V)
R89  ValueDisplayed: 10k  [0603]  (hidden comment: RC0603JR-0710KL)
R158  ValueDisplayed: 0  [0603]  (hidden comment: ERJ-3GEY0R00V)
R159  ValueDisplayed: 0  [0603]  (hidden comment: ERJ-3GEY0R00V)
R160  ValueDisplayed: 0  [0603]  (hidden comment: ERJ-3GEY0R00V)
R161  ValueDisplayed: 0  [0603]  (hidden comment: ERJ-3GEY0R00V)
R162  ValueDisplayed: 0  [0603]  (hidden comment: ERJ-3GEY0R00V)
R163  ValueDisplayed: 0  [0603]  (hidden comment: ERJ-3GEY0R00V)
R168  ValueDisplayed: 0  [0603]  (hidden comment: ERJ-3GEY0R00V)
R169  ValueDisplayed: 0  [0603]  (hidden comment: ERJ-3GEY0R00V)
R170  ValueDisplayed: 0  [0603]  (hidden comment: ERJ-3GEY0R00V)
TP5  5000  [Keystone5000]  (value not drawn)
TP6  5000  [Keystone5000]  (value not drawn)
U2  TLC372QDRG4  [D0008A_N]  (parts A,B of 2)
U5  OPA320AIDBVR  [DBV0005A_N]
U6  TLC372QDRG4  [D0008A_N]  (parts A,B of 2)
U7  TLC372QDRG4  [D0008A_N]  (parts A,B of 2)
U9  OPA320AIDBVR  [DBV0005A_N]
U11  OPA320AIDBVR  [DBV0005A_N]
U13  AMC1301DWVR  [DWV0008A]
U14  AMC1301DWVR  [DWV0008A]
U16  AMC1301DWVR  [DWV0008A]
U20  TL431BQDBZR  [DBZ0003A_N]
U21  TL431BQDBZR  [DBZ0003A_N]
U22  TL431BQDBZR  [DBZ0003A_N]

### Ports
I_U, I_V, I_W, OVERLOAD (out), U_PHASE (in), U_TOP_REF (in), V_PHASE (in), V_TOP_REF (in), VCC_U (in), VCC_V (in), VCC_W (in), W_PHASE (in), W_TOP_REF (in)

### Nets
1V65_REF: C26.2 C37.2 C52.2 R25.1 R40.1 R62.1
3V3: C13.1 C23.1 C31.1 C32.1 C34.1 C35.1 C44.1 C47.1 C48.1 C59.2 C60.2 C62.2 C65.2 C66.2 C69.2 R11.2 R20.2 R35.2 R48.2 U2.8(V+) U5.5(V+) U6.8(V+) U7.8(V+) U9.5(V+) U11.5(V+) U13.8(VDD2) U14.8(VDD2) U16.8(VDD2)
GND: C12.2 C13.2 C16.2 C17.2 C19.2 C23.2 C26.1 C27.2 C31.2 C32.2 C33.2 C34.2 C35.2 C37.1 C39.2 C42.2 C44.2 C47.2 C48.2 C52.1 C53.2 C59.1 C60.1 C62.1 C65.1 C66.1 C69.1 R21.1 R24.1 R32.1 R34.1 R39.1 R64.1 U2.4(V-) U5.2(V-) U6.4(V-) U7.4(V-) U9.2(V-) U11.2(V-) U13.5(GND2) U14.5(GND2) U16.5(GND2)
I_U: C12.1 R13.2 ; port I_U
I_V: C19.1 R17.2 ; port I_V
I_W: C17.1 R16.2 ; port I_W
OVERLOAD: R11.1 R158.2 R159.2 R160.2 R161.2 R162.2 R163.2 ; port OVERLOAD
U_PHASE: R86.1 ; port U_PHASE
U_TOP_REF: C80.1 C87.1 R78.2 R85.1 U13.4(GND1) U20.3(ANODE) ; port U_TOP_REF
V_PHASE: R88.1 ; port V_PHASE
V_TOP_REF: C86.1 C90.1 R84.2 R87.1 U16.4(GND1) U21.3(ANODE) ; port V_TOP_REF
VCC_U: R72.1 ; port VCC_U
VCC_V: R73.1 ; port VCC_V
VCC_W: R74.1 ; port VCC_W
VoutP_U: R22.1 R30.1 TP6.1 U13.7(VOUTP)
VoutP_V: R38.1 R61.1 U16.7(VOUTP)
VoutP_W: R46.1 R68.1 U14.7(VOUTP)
W_PHASE: R80.1 ; port W_PHASE
W_TOP_REF: C85.1 C89.1 R79.1 R89.2 U14.4(GND1) U22.3(ANODE) ; port W_TOP_REF
NetC16_1: C16.1 R15.2 U2.2(IN-) U2.5(IN+)
NetC27_1: C27.1 R24.2 R25.2 R26.2 U5.3(IN+)
NetC28_1: C28.1 R29.2 R31.1 U5.4(IN-)
NetC28_2: C28.2 R13.1 R27.2 R168.2 U5.1(OUT)
NetC29_1: C29.1 R29.1 R30.2
NetC29_2: C29.2 R26.1 R28.2
NetC33_1: C33.1 R33.2 U6.2(IN-) U6.5(IN+)
NetC39_1: C39.1 R39.2 R40.2 R51.2 U9.3(IN+)
NetC42_1: C42.1 R55.2 U7.2(IN-) U7.5(IN+)
NetC43_1: C43.1 R52.2 R57.1 U9.4(IN-)
NetC43_2: C43.2 R17.1 R50.2 R169.2 U9.1(OUT)
NetC45_1: C45.1 R49.1 R66.2 U11.4(IN-)
NetC45_2: C45.2 R16.1 R47.2 R170.2 U11.1(OUT)
NetC50_1: C50.1 R52.1 R61.2
NetC50_2: C50.2 R51.1 R60.2
NetC53_1: C53.1 R62.2 R64.2 R65.2 U11.3(IN+)
NetC54_1: C54.1 R66.1 R68.2
NetC54_2: C54.2 R65.1 R67.2
NetC80_2: C80.2 C87.2 R72.2 R75.1 U13.1(VDD1) U20.1(CATHODE)
NetC83_1: C83.1 R86.2 U13.2(VINP)
NetC83_2: C83.2 R85.2 U13.3(VINN)
NetC84_1: C84.1 R80.2 U14.2(VINP)
NetC84_2: C84.2 R79.2 U14.3(VINN)
NetC85_2: C85.2 C89.2 R74.2 R77.1 U14.1(VDD1) U22.1(CATHODE)
NetC86_2: C86.2 C90.2 R73.2 R76.1 U16.1(VDD1) U21.1(CATHODE)
NetC88_1: C88.1 R88.2 U16.2(VINP)
NetC88_2: C88.2 R87.2 U16.3(VINN)
NetR15_1: R15.1 R22.2 R168.1
NetR20_1: R20.1 R23.2 U2.3(IN+)
NetR21_2: R21.2 R23.1 U2.6(IN-)
NetR27_1: R27.1 R31.2
NetR28_1: R28.1 TP5.1 U13.6(VOUTN)
NetR32_2: R32.2 R36.1 U7.6(IN-)
NetR33_1: R33.1 R38.2 R169.1
NetR34_2: R34.2 R37.1 U6.6(IN-)
NetR35_1: R35.1 R37.2 U6.3(IN+)
NetR36_2: R36.2 R48.1 U7.3(IN+)
NetR46_2: R46.2 R55.1 R170.1
NetR47_1: R47.1 R49.2
NetR50_1: R50.1 R57.2
NetR60_1: R60.1 U16.6(VOUTN)
NetR67_1: R67.1 U14.6(VOUTN)
NetR75_2: R75.2 R78.1 U20.2(REF)
NetR76_2: R76.2 R84.1 U21.2(REF)
NetR77_2: R77.2 R89.1 U22.2(REF)
NetR158_1: R158.1 U2.1(OUT)
NetR159_1: R159.1 U2.7(OUT)
NetR160_1: R160.1 U6.1(OUT)
NetR161_1: R161.1 U6.7(OUT)
NetR162_1: R162.1 U7.1(OUT)
NetR163_1: R163.1 U7.7(OUT)

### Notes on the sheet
- Sensing for U-Phase
- Sensing for V-Phase
- Sensing for W-Phase

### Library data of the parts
C12 C17 C19 = 06031C152JAT2A: CAP, CERM, 1500 pF, 100 V, +/- 5%, X7R, 0603; Manufacturer: AVX; Polarized: N; CompType: Capacitor; Value: 1500pF; U/M: EA; Cap_F: 0.0000000015; Tolerance_%: 5; ESR_ohm: 0.229; Value1: 0.229 ohm; VDC_V: 100; Value2: 100V; TaMin_C: -55; TaMax_C: 125; AEC Category: Q200
C13 C23 C32 C34 C35 C44 = GRM188R71H104KA93D: CAP, CERM, 0.1 µF, 50 V, +/- 10%, X7R, 0603; Manufacturer: MuRata; Polarized: N; CompType: Capacitor; Value: 0.1uF; U/M: EA; Cap_F: 0.0000001; Tolerance_%: 10; Value1: Unknown; VDC_V: 50; Value2: 50V; TaMin_C: -55; TaMax_C: 125; SizeArea_mm2: 1.28; SizeAreaWB_mm2: 4.68; SizeX_mm: 1.6; SizeY_mm: 0.8; SizeZ_mm: 1; AEC Category: Q200
C16 C33 C42 C83 C84 C88 = 885012206040: as C46 on sheet TIDA-01541-E1_Gate driver and Module
C26 C31 C37 C47 C48 C52 C65 C66 C69 C87 C89 C90 = GRM188R71H104KA93D: as C36 on sheet TIDA-01541-E1_Gate driver and Module
C27-C29 C39 C43 C45 C50 C53 C54 = 06035A181JAT2A: CAP, CERM, 180 pF, 50 V, +/- 5%, C0G/NP0, 0603; Manufacturer: AVX; Polarized: N; CompType: Capacitor; Value: 180pF; U/M: EA; Cap_F: 0.00000000018; Tolerance_%: 5; ESR_ohm: 0.09; Value1: 0.09 ohm; VDC_V: 50; Value2: 50V; TaMin_C: -55; TaMax_C: 125; AEC Category: Q200
C59 C60 C62 C80 C85 C86 = C2012X5R1H475K125AB: as C55 on sheet TIDA-01541-E1_Gate driver and Module
R11 = RC0603JR-0710KL: RES, 10 k, 5%, 0.1 W, 0603; Manufacturer: Yageo America; CompType: Resistor; Value: 10k; Res_ohm: 10000; Value_Code: 10k0; Tolerance_%: 5; Power_W: 0.1; Value2: 0.1W; VDC_V: 50; TempCo: 100 ppm/C; EIA_Code: E24; U/M: EA; SizeArea_mm2: 1.28; SizeX_mm: 1.6; SizeY_mm: 0.8; SizeZ_mm: 1; AEC Category: Q200
R13 R16 R17 = RC0603FR-07100RL: RES, 100, 1%, 0.1 W, 0603; Manufacturer: Yageo America; CompType: Resistor; Value: 100; Value_Code: 100R; Tolerance_%: 1; Power_W: 0.1; Value2: 0.1W; VDC_V: 150; TempCo: 200 ppm/C; EIA_Code: E96; U/M: EA; AEC Category: Q200; SizeArea_mm2: 1.28; SizeX_mm: 1.6; SizeY_mm: 0.8
R15 R22 R31 R33 R38 R46 R49 R55 R57 R79 R80 R85-R88 R158-R163 R168-R170 = ERJ-3GEY0R00V: as R43 on sheet TIDA-01541-E1_Gate driver and Module
R20 R35 R48 = RC0603FR-073KL: RES, 3.00 k, 1%, 0.1 W, 0603; Manufacturer: Yageo America; CompType: Resistor; Value: 3.00k; Res_ohm: 3000; Value_Code: 3k00; Tolerance_%: 1; Power_W: 0.1; Value2: 0.1W; VDC_V: 150; TempCo: 200 ppm/C; U/M: EA; AEC Category: Q200; SizeArea_mm2: 1.28; SizeX_mm: 1.6; SizeY_mm: 0.8
R21 R32 R34 = ERJ-3EKF1501V: RES, 1.50 k, 1%, 0.1 W, 0603; Manufacturer: Panasonic; CompType: Resistor; Value: 1.50k; Res_ohm: 1500; Value_Code: 1k50; Tolerance_%: 1; Power_W: 0.1; Value2: 0.1W; VDC_V: 75; TempCo: 100 ppm/C; EIA_Code: E96; U/M: EA; AEC Category: Q200; SizeArea_mm2: 1.28; SizeX_mm: 1.6; SizeY_mm: 0.8
R23 R36 R37 = RT0603BRD077K15L: RES, 7.15 k, 0.1%, 0.1 W, 0603; Manufacturer: Yageo America; CompType: Resistor; Value: 7.15k; Res_ohm: 7150; Value_Code: 7k15; Tolerance_%: 0.1; Value2: 0.1W; VDC_V: 75; TempCo: 25 ppm/C; EIA_Code: E192; U/M: EA; AEC Category: Q200; SizeArea_mm2: 1.28; SizeX_mm: 1.6; SizeY_mm: 0.8; SizeZ_mm: 1
R24 R25 R39 R40 R62 R64 = ERJ-3EKF7501V: RES, 7.50 k, 1%, 0.1 W, 0603; Manufacturer: Panasonic; CompType: Resistor; Value: 7.50k; Res_ohm: 7500; Value_Code: 7k50; Tolerance_%: 1; Power_W: 0.1; Value2: 0.1W; VDC_V: 75; TempCo: 100 ppm/C; EIA_Code: E96; U/M: EA; AEC Category: Q200; SizeArea_mm2: 1.28; SizeX_mm: 1.6; SizeY_mm: 0.8
R26 R28-R30 R51 R52 R60 R61 R65-R68 = RC0603FR-074K7L: RES, 4.70 k, 1%, 0.1 W, 0603; Manufacturer: Yageo America; CompType: Resistor; Value: 4.70k; Res_ohm: 4700; Value_Code: 4k70; Tolerance_%: 1; Power_W: 0.1; Value2: 0.1W; VDC_V: 150; TempCo: 200 ppm/C; U/M: EA; AEC Category: Q200
R27 R47 R50 = ERJ-3EKF7501V: RES, 7.50 k, 1%, 0.1 W, 0603; Manufacturer: Panasonic; CompType: Resistor; Value: 7.50k; Res_ohm: 7500; Value_Code: 7k50; Tolerance_%: 1; Power_W: 0.1; Value2: 0.1W; VDC_V: 75; TempCo: 100 ppm/C; EIA_Code: E96; U/M: EA; AEC Category: Q200
R72-R74 = CRCW0805820RJNEA: RES, 820, 5%, 0.125 W, 0805; Manufacturer: Vishay-Dale; CompType: Resistor; Value: 820; Value_Code: 820R; Tolerance_%: 5; Power_W: 0.125; Value2: 0.125W; VDC_V: 150; TempCo: 200 ppm/C; EIA_Code: E24; U/M: EA; AEC Category: Q200
R75-R78 R84 R89 = RC0603JR-0710KL: as R44 on sheet TIDA-01541-E1_Gate driver and Module
TP5 TP6 = 5000: Test Point, Miniature, Red, TH; Manufacturer: Keystone; CompType: Test Point Loop; ContactFinish: Silver
U2 U6 U7 = TLC372QDR: LinCMOS Dual Differential Comparators, D0008A; Manufacturer: Texas Instruments; SymbolCreator: a0411947; CompType: IC; U/M: EA
U5 U9 U11 = OPA320AIDBVR: Precision, 20 MHz, 0.9 pA Ib, RRIO, CMOS Operational Amplifier, 1.8 to 5.5 V, -40 to 125 degC, 5-pin SOT23 (DBV0005A), Green (RoHS & no Sb/Br); Manufacturer: Texas Instruments; Alternate PartNumber: Equivalent; CMRR(Min)(dB): 100; IIB(Max)(pA): 0.9; Iq per channel(Max)(mA): 1.75; Number of Channels: 2; Offset Drift(Typ)(uV/C): 1.5; Slew Rate(Typ)(V/us): 10; Sub Family: High Output Current Amplifier (>=50mA), Low Input Bias Current Amp (<=10pA), Low Noise Amp (<=10nV/rtHz), Low Offset Voltage Amplifier (<=500uV), Low Supply Voltage Amplifier (<=2.7V), Precision Amplifier; Total Supply Voltage(Max)(+5V is 5, +/-5V is 10): 5.5; Total Supply Voltage(Min)(+5V is 5, +/-5V is 10): 1.8; Vio (25C)(Max)(mV): 0.15; Vn at 1kHz(Typ)(nV/rtHz): 8.5
U13 U14 U16 = AMC1301DWVR: 200 kHz, Fully-Differential Isolation Amplifier, DWV0008A; Manufacturer: Texas Instruments; SymbolCreator: Altium; CompType: IC; U/M: EA
U20-U22 = TL431BQDBZT: Adjustable Precision Shunt Regulator, 34 ppm / degC, 100 mA, -40 to 125 degC, 3-pin SOT-23 (DBZ), Green (RoHS & no Sb/Br); Manufacturer: Texas Instruments; Alternate PartNumber: Equivalent; Initial Accuracy @ 25/deg C(%): 0.5; Iout/Iz(Max)(mA): 100; Min Iz for Regulation(uA): 600; Rating: Catalog; SubFamily: Shunt Voltage Reference; Temp Coeff(Max)(ppm/ degree C): 92; Temp Coeff(Typ)(ppm/ degree C): 34; VO Adj(Max)(V): 36; VO Adj(Min)(V): 2.495

## Sheet TIDA-01541-E1_DC BUS and TEMP Sense.SchDoc: DC Bus and TEMP sense
size 431 x 279 mm; Date: Not shown in title block; ApprovedBy: Not shown in title block; CheckedBy: Not shown in title block; Author: Not shown in title block; CompanyName: Not shown in title block; DrawnBy: NN; Engineer: Not shown in title block; Organization: Not shown in title block; Address1: Not shown in title block; Address2: Not shown in title block; Address3: Not shown in title block; Address4: Not shown in title block; DocumentNumber: 1; Revision: Use project parameter SCH_Rev; SheetNumber: 4; SheetTotal: 6; PageSetup: Record=PageOptions¦CenterHorizontal=True¦CenterVertical=True¦PrintScale=1.00¦XCorrection=1.00¦YCorrection=1.00¦PrintKind=0¦BorderSize=5000000¦LeftOffset=0¦BottomOffset=0¦Orientation=2¦PaperLength=1000¦PaperWidth=1000¦Scale=100¦PaperSource=15¦PrintQuality=600¦MediaType=1¦DitherType=10¦PaperKind=Letter¦PrintScaleMode=1
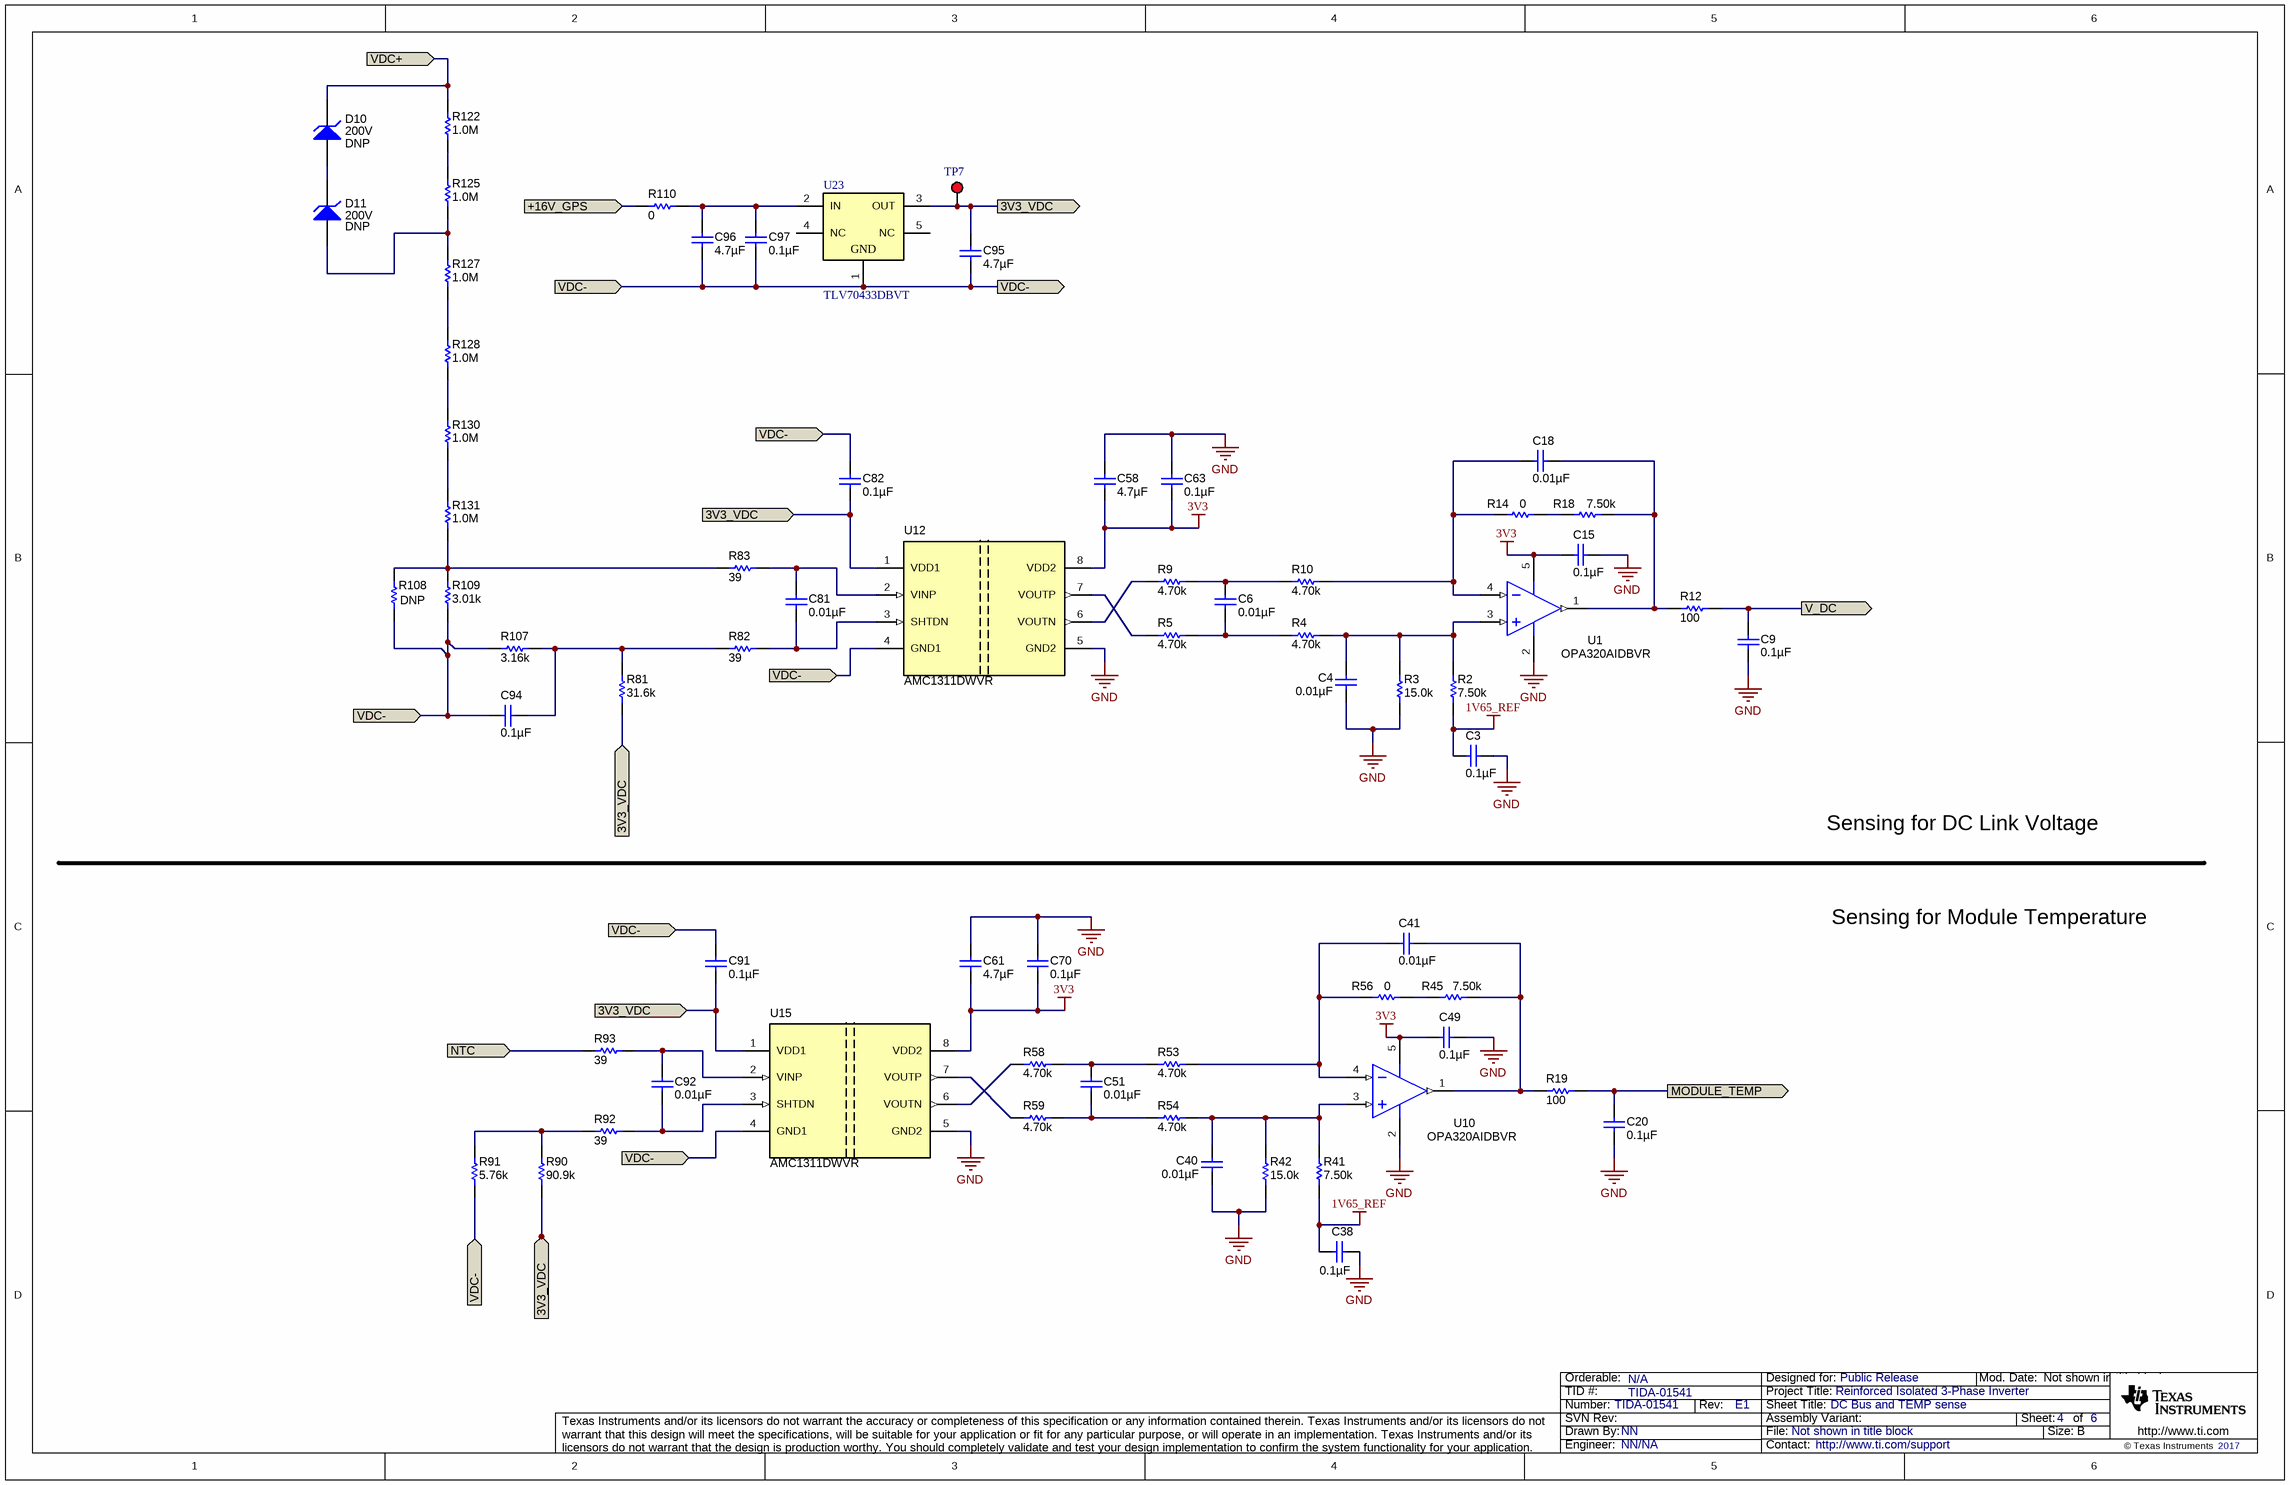
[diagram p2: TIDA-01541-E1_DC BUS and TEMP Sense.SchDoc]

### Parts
C3  ValueDisplayed: 0.1µF  [0603]  (hidden comment: GRM188R71H104KA93D)
C4  ValueDisplayed: 0.01µF  [0603]  (hidden comment: 885012206040)
C6  ValueDisplayed: 0.01µF  [0603]  (hidden comment: 885012206040)
C9  ValueDisplayed: 0.1µF  [0603]  (hidden comment: GRM188R71H104KA93D)
C15  ValueDisplayed: 0.1µF  [0603]  (hidden comment: GRM188R71H104KA93D)
C18  ValueDisplayed: 0.01µF  [0603]  (hidden comment: 885012206040)
C20  ValueDisplayed: 0.1µF  [0603]  (hidden comment: GRM188R71H104KA93D)
C38  ValueDisplayed: 0.1µF  [0603]  (hidden comment: GRM188R71H104KA93D)
C40  ValueDisplayed: 0.01µF  [0603]  (hidden comment: 885012206040)
C41  ValueDisplayed: 0.01µF  [0603]  (hidden comment: 885012206040)
C49  ValueDisplayed: 0.1µF  [0603]  (hidden comment: GRM188R71H104KA93D)
C51  ValueDisplayed: 0.01µF  [0603]  (hidden comment: 885012206040)
C58  ValueDisplayed: 4.7µF  [0805_HV]  (hidden comment: C2012X5R1H475K125AB)
C61  ValueDisplayed: 4.7µF  [0805_HV]  (hidden comment: C2012X5R1H475K125AB)
C63  ValueDisplayed: 0.1µF  [0603]  (hidden comment: GRM188R71H104KA93D)
C70  ValueDisplayed: 0.1µF  [0603]  (hidden comment: GRM188R71H104KA93D)
C81  ValueDisplayed: 0.01µF  [0603]  (hidden comment: 885012206040)
C82  ValueDisplayed: 0.1µF  [0603]  (hidden comment: GRM188R71H104KA93D)
C91  ValueDisplayed: 0.1µF  [0603]  (hidden comment: GRM188R71H104KA93D)
C92  ValueDisplayed: 0.01µF  [0603]  (hidden comment: 885012206040)
C94  ValueDisplayed: 0.1µF  [0603]  (hidden comment: GRM188R71H104KA93D)
C95  ValueDisplayed: 4.7µF  [0805_HV]  (hidden comment: C2012X5R1H475K125AB)
C96  ValueDisplayed: 4.7µF  [0805_HV]  (hidden comment: C2012X5R1H475K125AB)
C97  ValueDisplayed: 0.1µF  [0603]  (hidden comment: GRM188R71H104KA93D)
D10  value 200V  [SMB]  (hidden comment: 1SMB5956BT3G)
D11  value 200V  [SMB]  (hidden comment: 1SMB5956BT3G)
R2  ValueDisplayed: 7.50k  [0603]  (hidden comment: ERJ-3EKF7501V)
R3  ValueDisplayed: 15.0k  [0603]  (hidden comment: RC0603FR-0715KL)
R4  ValueDisplayed: 4.70k  [0603]  (hidden comment: RC0603FR-074K7L)
R5  ValueDisplayed: 4.70k  [0603]  (hidden comment: RC0603FR-074K7L)
R9  ValueDisplayed: 4.70k  [0603]  (hidden comment: RC0603FR-074K7L)
R10  ValueDisplayed: 4.70k  [0603]  (hidden comment: RC0603FR-074K7L)
R12  ValueDisplayed: 100  [0603]  (hidden comment: RC0603FR-07100RL)
R14  ValueDisplayed: 0  [0603]  (hidden comment: ERJ-3GEY0R00V)
R18  ValueDisplayed: 7.50k  [0603]  (hidden comment: ERJ-3EKF7501V)
R19  ValueDisplayed: 100  [0603]  (hidden comment: RC0603FR-07100RL)
R41  ValueDisplayed: 7.50k  [0603]  (hidden comment: ERJ-3EKF7501V)
R42  ValueDisplayed: 15.0k  [0603]  (hidden comment: RC0603FR-0715KL)
R45  ValueDisplayed: 7.50k  [0603]  (hidden comment: ERJ-3EKF7501V)
R53  ValueDisplayed: 4.70k  [0603]  (hidden comment: RC0603FR-074K7L)
R54  ValueDisplayed: 4.70k  [0603]  (hidden comment: RC0603FR-074K7L)
R56  ValueDisplayed: 0  [0603]  (hidden comment: ERJ-3GEY0R00V)
R58  ValueDisplayed: 4.70k  [0603]  (hidden comment: RC0603FR-074K7L)
R59  ValueDisplayed: 4.70k  [0603]  (hidden comment: RC0603FR-074K7L)
R81  ValueDisplayed: 31.6k  [0603]  (hidden comment: CRCW060331K6FKEA)
R82  ValueDisplayed: 39  [0603]  (hidden comment: CRCW060339R0JNEA)
R83  ValueDisplayed: 39  [0603]  (hidden comment: CRCW060339R0JNEA)
R90  ValueDisplayed: 90.9k  [0603]  (hidden comment: RC0603FR-0790K9L)
R91  ValueDisplayed: 5.76k  [0603]  (hidden comment: CRCW06035K76FKEA)
R92  ValueDisplayed: 39  [0603]  (hidden comment: CRCW060339R0JNEA)
R93  ValueDisplayed: 39  [0603]  (hidden comment: CRCW060339R0JNEA)
R107  ValueDisplayed: 3.16k  [0603]  (hidden comment: RC0603FR-073K16L)
R108  CRCW06032K61FKEA  [0603]  (value not drawn)
R109  ValueDisplayed: 3.01k  [0603]  (hidden comment: RC0603FR-073K01L)
R110  ValueDisplayed: 0  [0603]  (hidden comment: ERJ-3GEY0R00V)
R122  ValueDisplayed: 1.0M  [0805_HV]  (hidden comment: CRCW08051M00JNEA)
R125  ValueDisplayed: 1.0M  [0805_HV]  (hidden comment: CRCW08051M00JNEA)
R127  ValueDisplayed: 1.0M  [0805_HV]  (hidden comment: CRCW08051M00JNEA)
R128  ValueDisplayed: 1.0M  [0805_HV]  (hidden comment: CRCW08051M00JNEA)
R130  ValueDisplayed: 1.0M  [0805_HV]  (hidden comment: CRCW08051M00JNEA)
R131  ValueDisplayed: 1.0M  [0805_HV]  (hidden comment: CRCW08051M00JNEA)
TP7  5000  [Keystone5000]  (value not drawn)
U1  OPA320AIDBVR  [DBV0005A_N]
U10  OPA320AIDBVR  [DBV0005A_N]
U12  AMC1311DWVR  [DWV0008A]
U15  AMC1311DWVR  [DWV0008A]
U23  TLV70433DBVT  [DBV0005A_N]

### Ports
3V3_VDC (in), 3V3_VDC (out), +16V_GPS (in), MODULE_TEMP (out), NTC (in), V_DC (out), VDC+ (in), VDC- (in), VDC- (out)

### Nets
1V65_REF: C3.2 C38.2 R2.1 R41.1
3V3: C15.1 C49.1 C58.2 C61.2 C63.2 C70.2 U1.5(V+) U10.5(V+) U12.8(VDD2) U15.8(VDD2)
GND: C3.1 C4.2 C9.2 C15.2 C20.2 C38.1 C40.2 C49.2 C58.1 C61.1 C63.1 C70.1 R3.1 R42.1 U1.2(V-) U10.2(V-) U12.5(GND2) U15.5(GND2)
3V3_VDC: C82.2 C91.2 C95.1 R81.1 R90.1 TP7.1 U12.1(VDD1) U15.1(VDD1) U23.3(OUT) ; port 3V3_VDC
+16V_GPS: R110.1 ; port +16V_GPS
MODULE_TEMP: C20.1 R19.2 ; port MODULE_TEMP
NTC: R93.1 ; port NTC
V_DC: C9.1 R12.2 ; port V_DC
VDC+: D10.1(K) R122.2 ; port VDC+
VDC-: C82.1 C91.1 C94.1 C95.2 C96.2 C97.2 R91.1 R107.1 R108.1 R109.1 U12.4(GND1) U15.4(GND1) U23.1(GND) ; port VDC-
NetC4_1: C4.1 R2.2 R3.2 R4.2 U1.3(IN+)
NetC6_1: C6.1 R9.2 R10.1
NetC6_2: C6.2 R4.1 R5.2
NetC18_1: C18.1 R10.2 R14.1 U1.4(IN-)
NetC18_2: C18.2 R12.1 R18.2 U1.1(OUT)
NetC40_1: C40.1 R41.2 R42.2 R54.2 U10.3(IN+)
NetC41_1: C41.1 R53.2 R56.1 U10.4(IN-)
NetC41_2: C41.2 R19.1 R45.2 U10.1(OUT)
NetC51_1: C51.1 R53.1 R58.2
NetC51_2: C51.2 R54.1 R59.2
NetC81_1: C81.1 R83.2 U12.2(VINP)
NetC81_2: C81.2 R82.2 U12.3(SHTDN)
NetC92_1: C92.1 R93.2 U15.2(VINP)
NetC92_2: C92.2 R92.2 U15.3(SHTDN)
NetC94_2: C94.2 R81.2 R82.1 R107.2
NetC96_1: C96.1 C97.1 R110.2 U23.2(IN)
NetD10_2: D10.2(A) D11.1(K)
NetD11_2: D11.2(A) R125.1 R127.2
NetR5_1: R5.1 U12.7(VOUTP)
NetR9_1: R9.1 U12.6(VOUTN)
NetR14_2: R14.2 R18.1
NetR45_1: R45.1 R56.2
NetR58_1: R58.1 U15.6(VOUTN)
NetR59_1: R59.1 U15.7(VOUTP)
NetR83_1: R83.1 R108.2 R109.2 R131.1
NetR90_2: R90.2 R91.2 R92.1
NetR122_1: R122.1 R125.2
NetR127_1: R127.1 R128.2
NetR128_1: R128.1 R130.2
NetR130_1: R130.1 R131.2

Not connected (* = marked no-connect by the designer): U23 4(NC) 5(NC)

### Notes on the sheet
- Sensing for DC Link Voltage
- Sensing for Module Temperature

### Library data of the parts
C3 C9 C15 C20 C38 C49 C63 C70 C82 C91 C94 C97 = GRM188R71H104KA93D: as C36 on sheet TIDA-01541-E1_Gate driver and Module
C4 C6 C18 C40 C41 C51 C81 C92 = 885012206040: CAP, CERM, 0.01 µF, 16 V, +/- 10%, X7R, 0603; Manufacturer: Wurth Elektronik; Polarized: N; CompType: Capacitor; Value: 0.01uF; U/M: EA; Cap_F: 0.00000001; Tolerance_%: 10; Value1: Unknown; VDC_V: 16; Value2: 16V; TaMin_C: -55; TaMax_C: 125; AEC Category: Q200
C58 C61 C95 C96 = C2012X5R1H475K125AB: as C55 on sheet TIDA-01541-E1_Gate driver and Module
D10 D11 = 1SMB5956BT3G: Diode, Zener, 200 V, 550 mW, SMB; Manufacturer: ON Semiconductor; SymbolCreator: a0412235; U/M: EA; Power_W: 0.55; Vz_V: 200; Value1: 0.55W; RJA_CperW: 226; AEC Category: Q101
R2 R41 R45 = ERJ-3EKF7501V: as R24 on sheet TIDA-01541-E1_Current sense
R3 R42 = RC0603FR-0715KL: RES, 15.0 k, 1%, 0.1 W, 0603; Manufacturer: Yageo America; CompType: Resistor; Value: 15.0k; Res_ohm: 15000; Value_Code: 15k0; Tolerance_%: 1; Power_W: 0.1; Value2: 0.1W; VDC_V: 150; TempCo: 200 ppm/C; EIA_Code: E96; U/M: EA; AEC Category: Q200; SizeArea_mm2: 1.28; SizeX_mm: 1.6; SizeY_mm: 0.8
R4 R5 R9 R10 R53 R54 R58 R59 = RC0603FR-074K7L: as R26 on sheet TIDA-01541-E1_Current sense
R12 R19 = RC0603FR-07100RL: as R13 on sheet TIDA-01541-E1_Current sense
R14 R56 R110 = ERJ-3GEY0R00V: as R43 on sheet TIDA-01541-E1_Gate driver and Module
R18 = ERJ-3EKF7501V: as R27 on sheet TIDA-01541-E1_Current sense
R81 = CRCW060331K6FKEA: RES, 31.6 k, 1%, 0.1 W, 0603; Manufacturer: Vishay-Dale; CompType: Resistor; Value: 31.6k; Res_ohm: 31600; Value_Code: 31k6; Tolerance_%: 1; Power_W: 0.1; Value2: 0.1W; VDC_V: 75; TempCo: 100 ppm/C; EIA_Code: E96; U/M: EA; AEC Category: Q200
R82 R83 R92 R93 = CRCW060339R0JNEA: RES, 39, 5%, 0.1 W, 0603; Manufacturer: Vishay-Dale; CompType: Resistor; Value: 39; Value_Code: 39R0; Tolerance_%: 5; Power_W: 0.1; Value2: 0.1W; VDC_V: 75; TempCo: 200 ppm/C; EIA_Code: E24; U/M: EA; AEC Category: Q200
R90 = RC0603FR-0790K9L: RES, 90.9 k, 1%, 0.1 W, 0603; Manufacturer: Yageo America; CompType: Resistor; Value: 90.9k; Res_ohm: 90900; Value_Code: 90k9; Tolerance_%: 1; Power_W: 0.1; Value2: 0.1W; VDC_V: 150; TempCo: 200 ppm/C; EIA_Code: E96; U/M: EA; AEC Category: Q200; SizeArea_mm2: 1.28; SizeX_mm: 1.6; SizeY_mm: 0.8
R91 = CRCW06035K76FKEA: RES, 5.76 k, 1%, 0.1 W, 0603; Manufacturer: Vishay-Dale; CompType: Resistor; Value: 5.76k; Res_ohm: 5760; Value_Code: 5k76; Tolerance_%: 1; Power_W: 0.1; Value2: 0.1W; VDC_V: 75; TempCo: 100 ppm/C; EIA_Code: E96; U/M: EA; AEC Category: Q200
R107 = RC0603FR-073K16L: RES, 3.16 k, 1%, 0.1 W, 0603; Manufacturer: Yageo America; CompType: Resistor; Value: 3.16k; Res_ohm: 3160; Value_Code: 3k16; Tolerance_%: 1; Power_W: 0.1; Value2: 0.1W; VDC_V: 150; TempCo: 200 ppm/C; EIA_Code: E96; U/M: EA; AEC Category: Q200
R108 = CRCW06032K61FKEA: RES, 2.61 k, 1%, 0.1 W, 0603; Manufacturer: Vishay-Dale; CompType: Resistor; Value: 2.61k; Res_ohm: 2610; Value_Code: 2k61; Tolerance_%: 1; Power_W: 0.1; Value2: 0.1W; VDC_V: 75; TempCo: 100 ppm/C; EIA_Code: E96; U/M: EA; AEC Category: Q200
R109 = RC0603FR-073K01L: RES, 3.01 k, 1%, 0.1 W, 0603; Manufacturer: Yageo America; CompType: Resistor; Value: 3.01k; Res_ohm: 3010; Value_Code: 3k01; Tolerance_%: 1; Power_W: 0.1; Value2: 0.1W; VDC_V: 150; TempCo: 200 ppm/C; EIA_Code: E96; U/M: EA; AEC Category: Q200
R122 R125 R127 R128 R130 R131 = CRCW08051M00JNEA: RES, 1.0 M, 5%, 0.125 W, 0805; Manufacturer: Vishay-Dale; CompType: Resistor; Value: 1.0Meg; Res_ohm: 1000000; Value_Code: 1M00; Tolerance_%: 5; Power_W: 0.125; Value2: 0.125W; VDC_V: 150; TempCo: 200 ppm/C; EIA_Code: E24; U/M: EA; AEC Category: Q200
TP7 = 5000: as TP5 on sheet TIDA-01541-E1_Current sense
U1 U10 = OPA320AIDBVR: as U5 on sheet TIDA-01541-E1_Current sense
U12 U15 = CMP-0013503-2: Precision, 2-V Input, Reinforced Isolated Amplifier, DWV0008A (SOIC-8); Manufacturer: Texas Instruments; SizeX_mm: 11.5; SizeY_mm: 5.85; CompType: IC; SizeZ_mm: 2.8; SizeArea_mm2: 67.275; SizeAreaWB_mm2: 105.975; U/M: EA
U23 = TLV70433DBVR: Single Output LDO, 150 mA, Fixed 3.3 V Output, 2.5 to 24 V Input, with Ultra-Low IQ, 5-pin SOT-23 (DBV), -40 to 125 degC, Green (RoHS & no Sb/Br); Manufacturer: Texas Instruments; Alternate PartNumber: Equivalent; Accuracy(%): 2; Fixed Output Options(V): 3.3; Iout(Max)(A): 0.15; Iq(Typ)(mA): 0.003; SubFamily: Single Channel LDO; Vdo(Typ)(mV): 400; Vin(Max)(V): 24; Vin(Min)(V): 2.5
